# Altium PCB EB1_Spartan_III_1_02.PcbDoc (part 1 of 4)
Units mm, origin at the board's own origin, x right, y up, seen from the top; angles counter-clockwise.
Board outline 165.1 x 115.01 mm, 6 copper layers (Top Layer, MidLayer1, VCC Plane, GND Plane, MidLayer2, Bottom Layer); 356 components, 386 nets, 1788 pads, 779 vias.
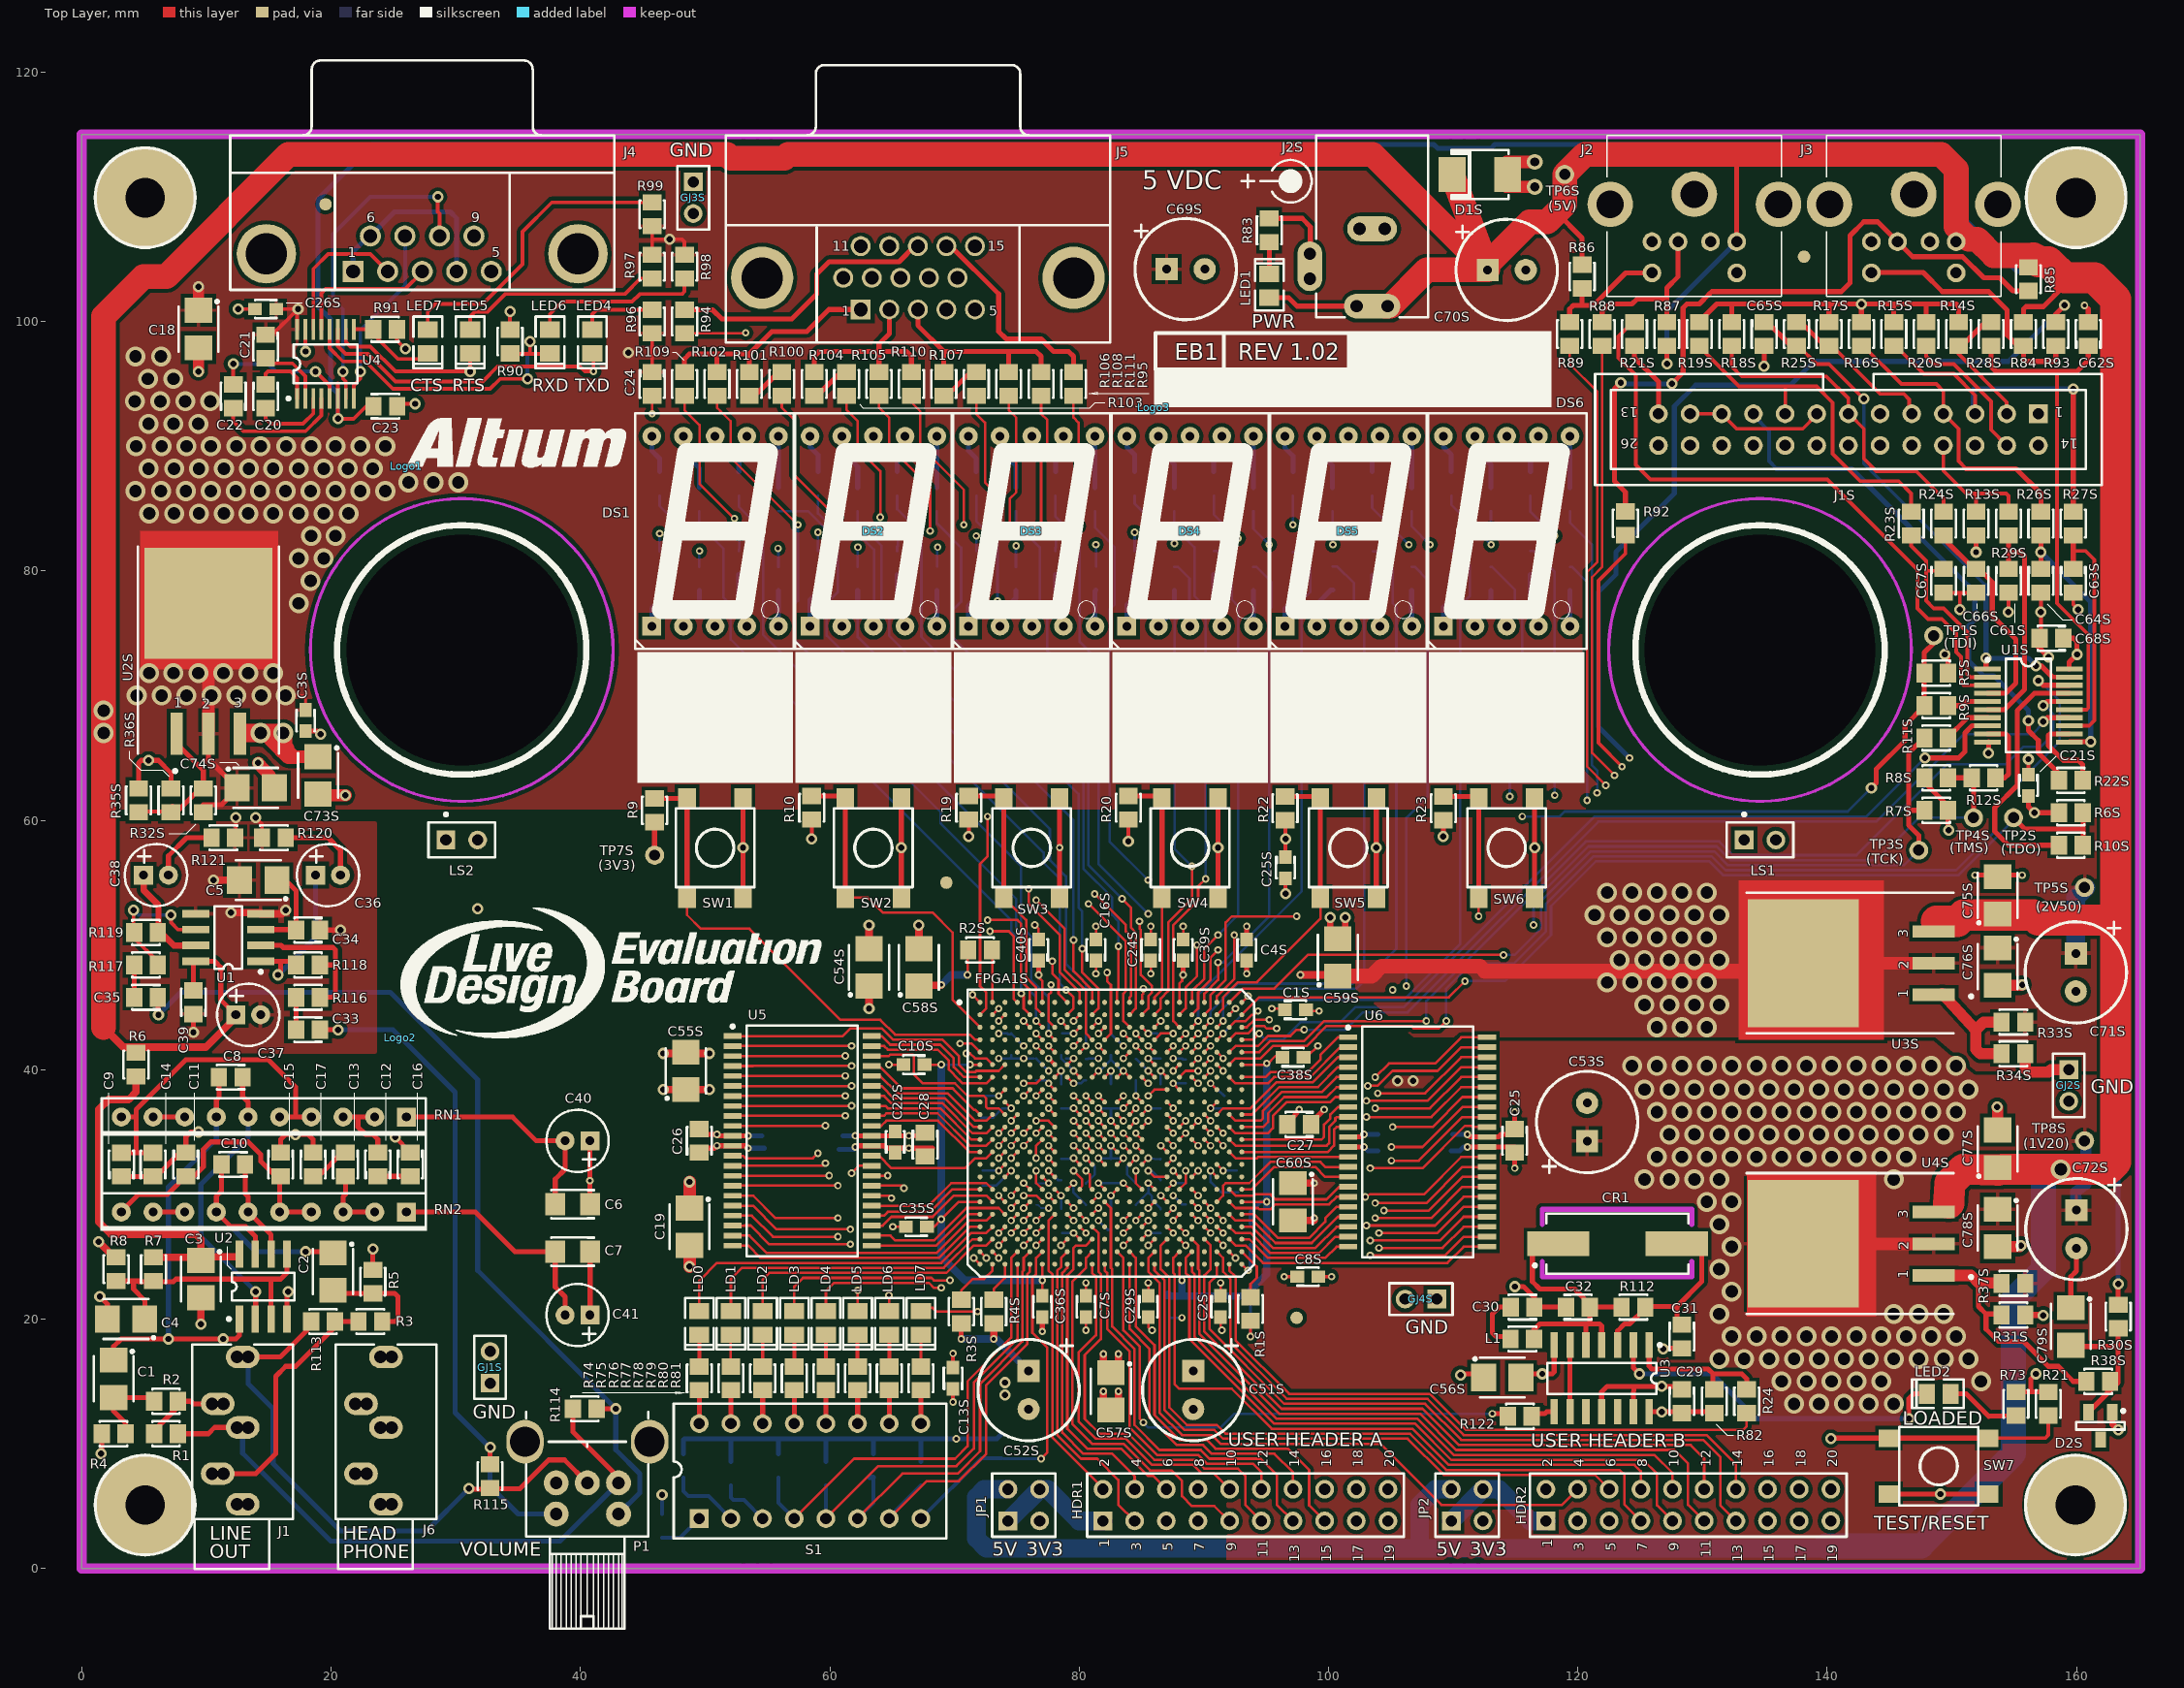
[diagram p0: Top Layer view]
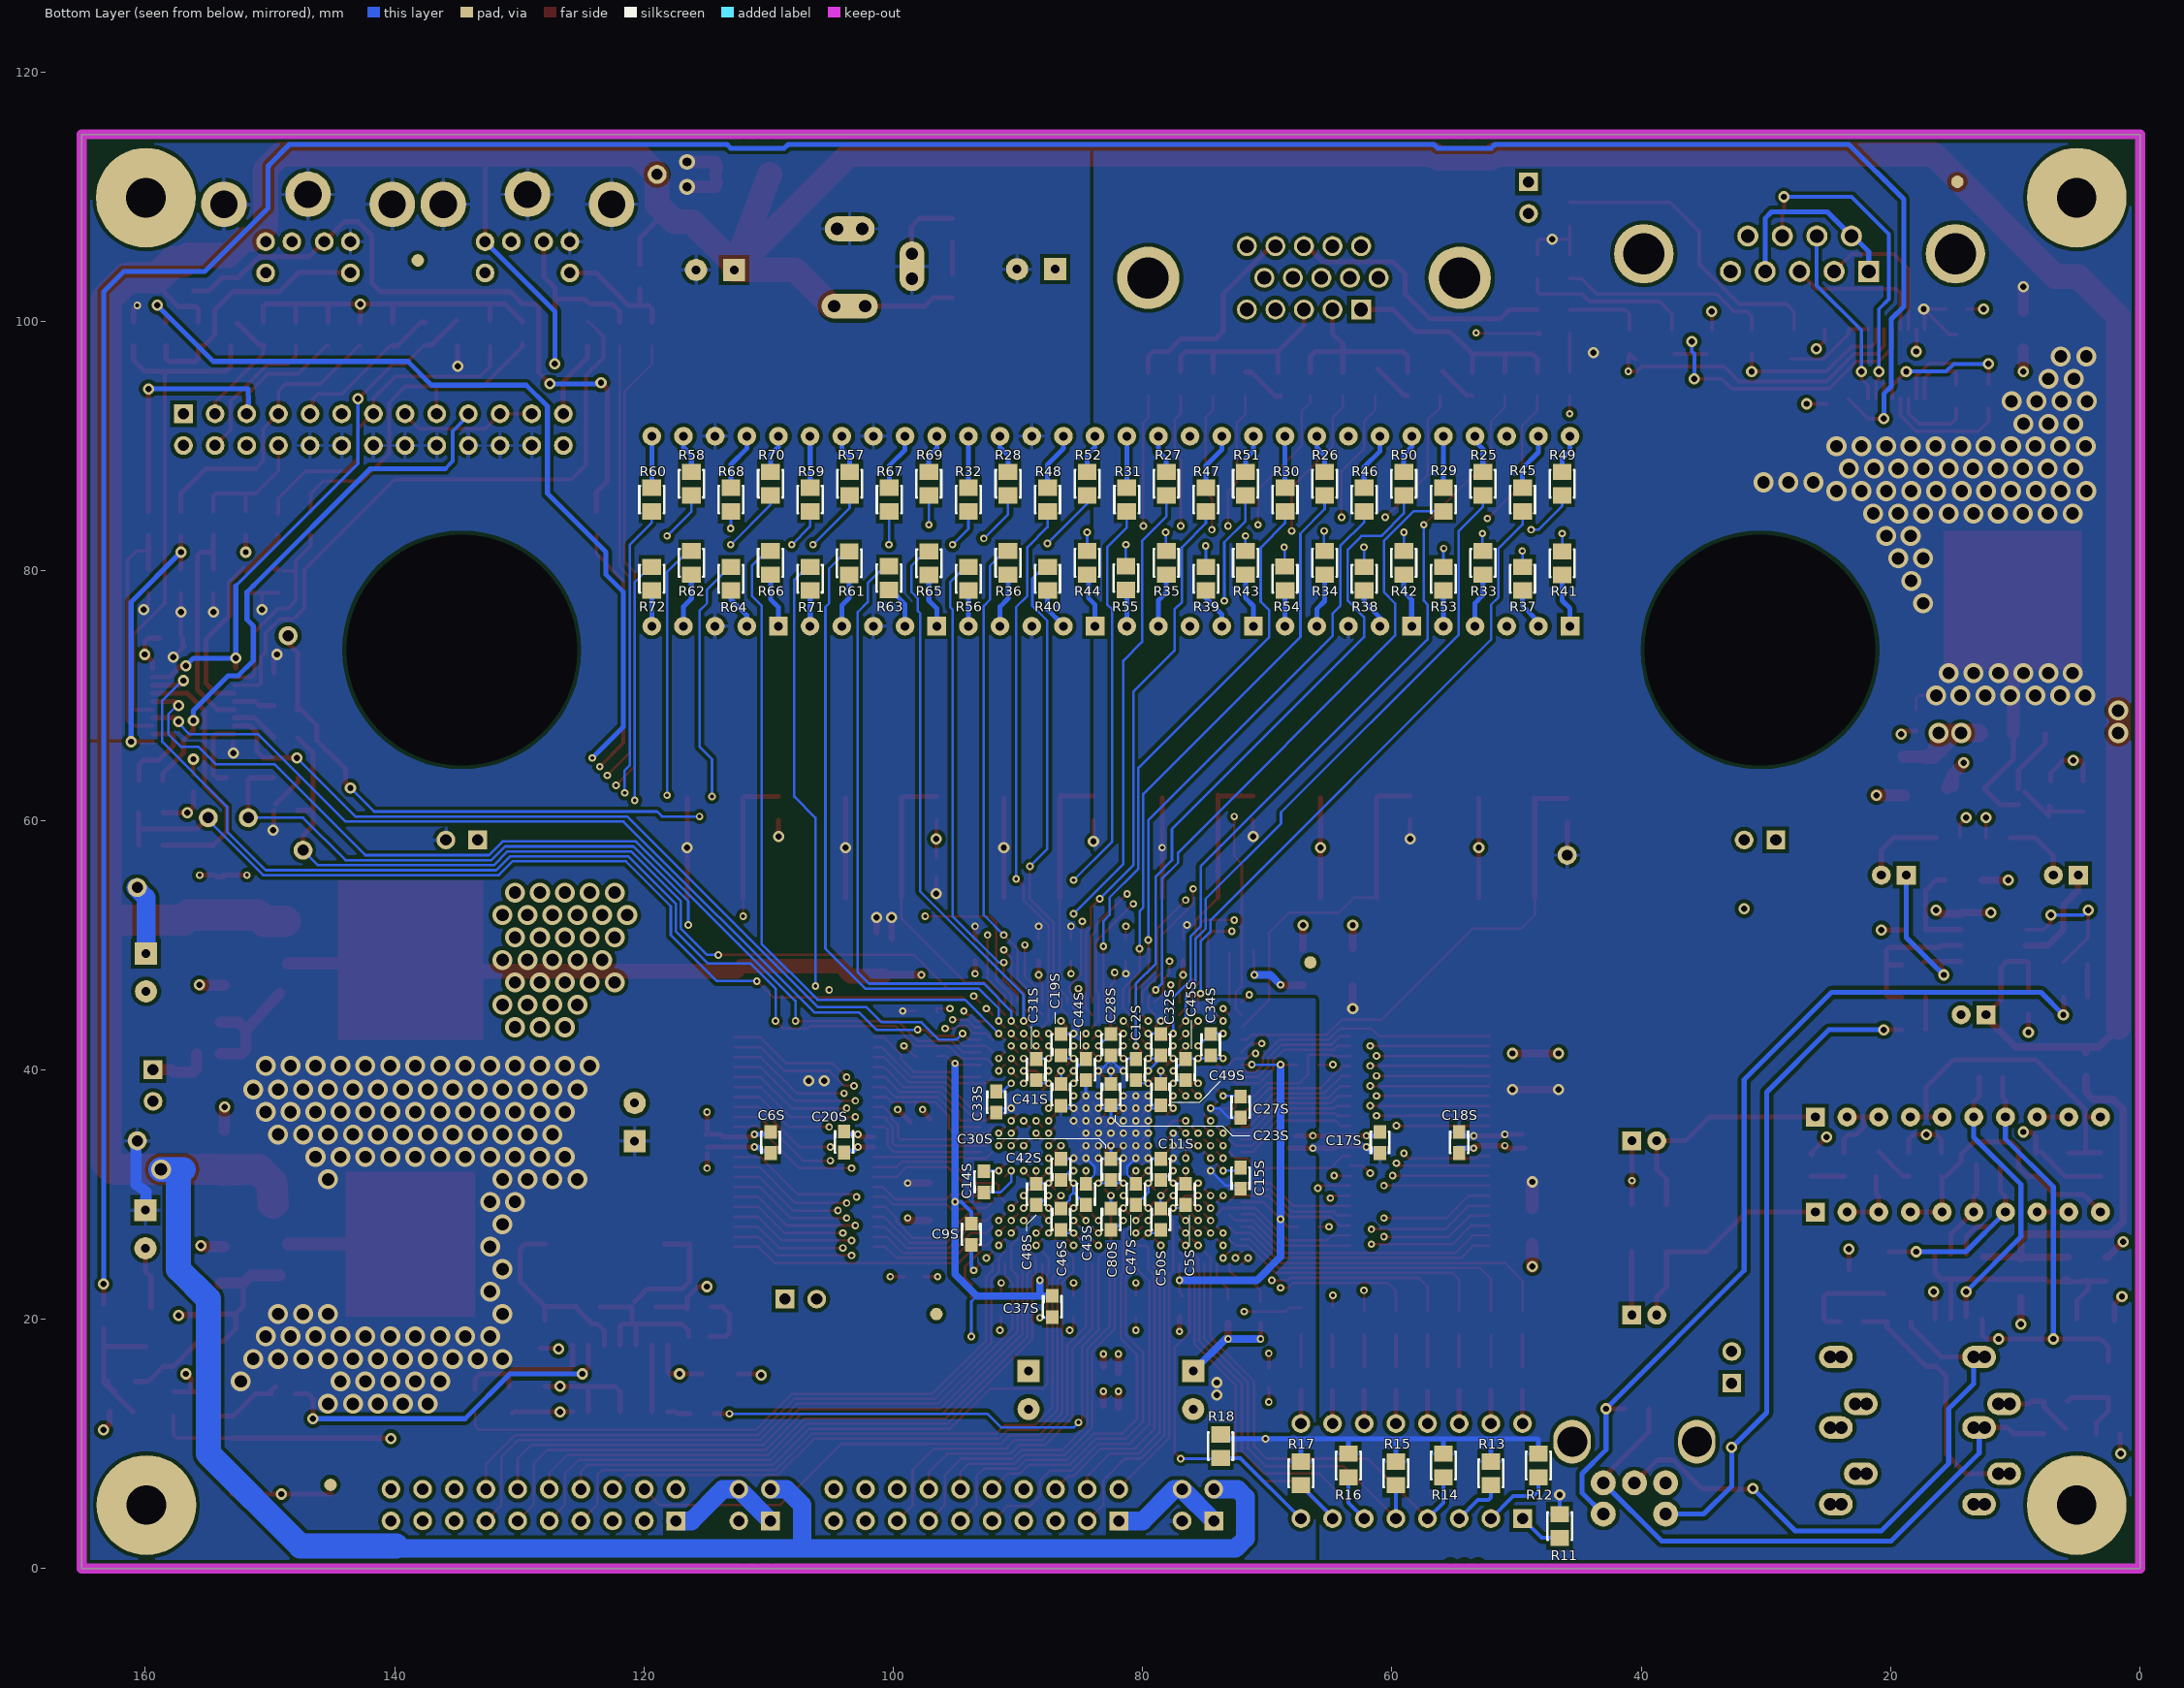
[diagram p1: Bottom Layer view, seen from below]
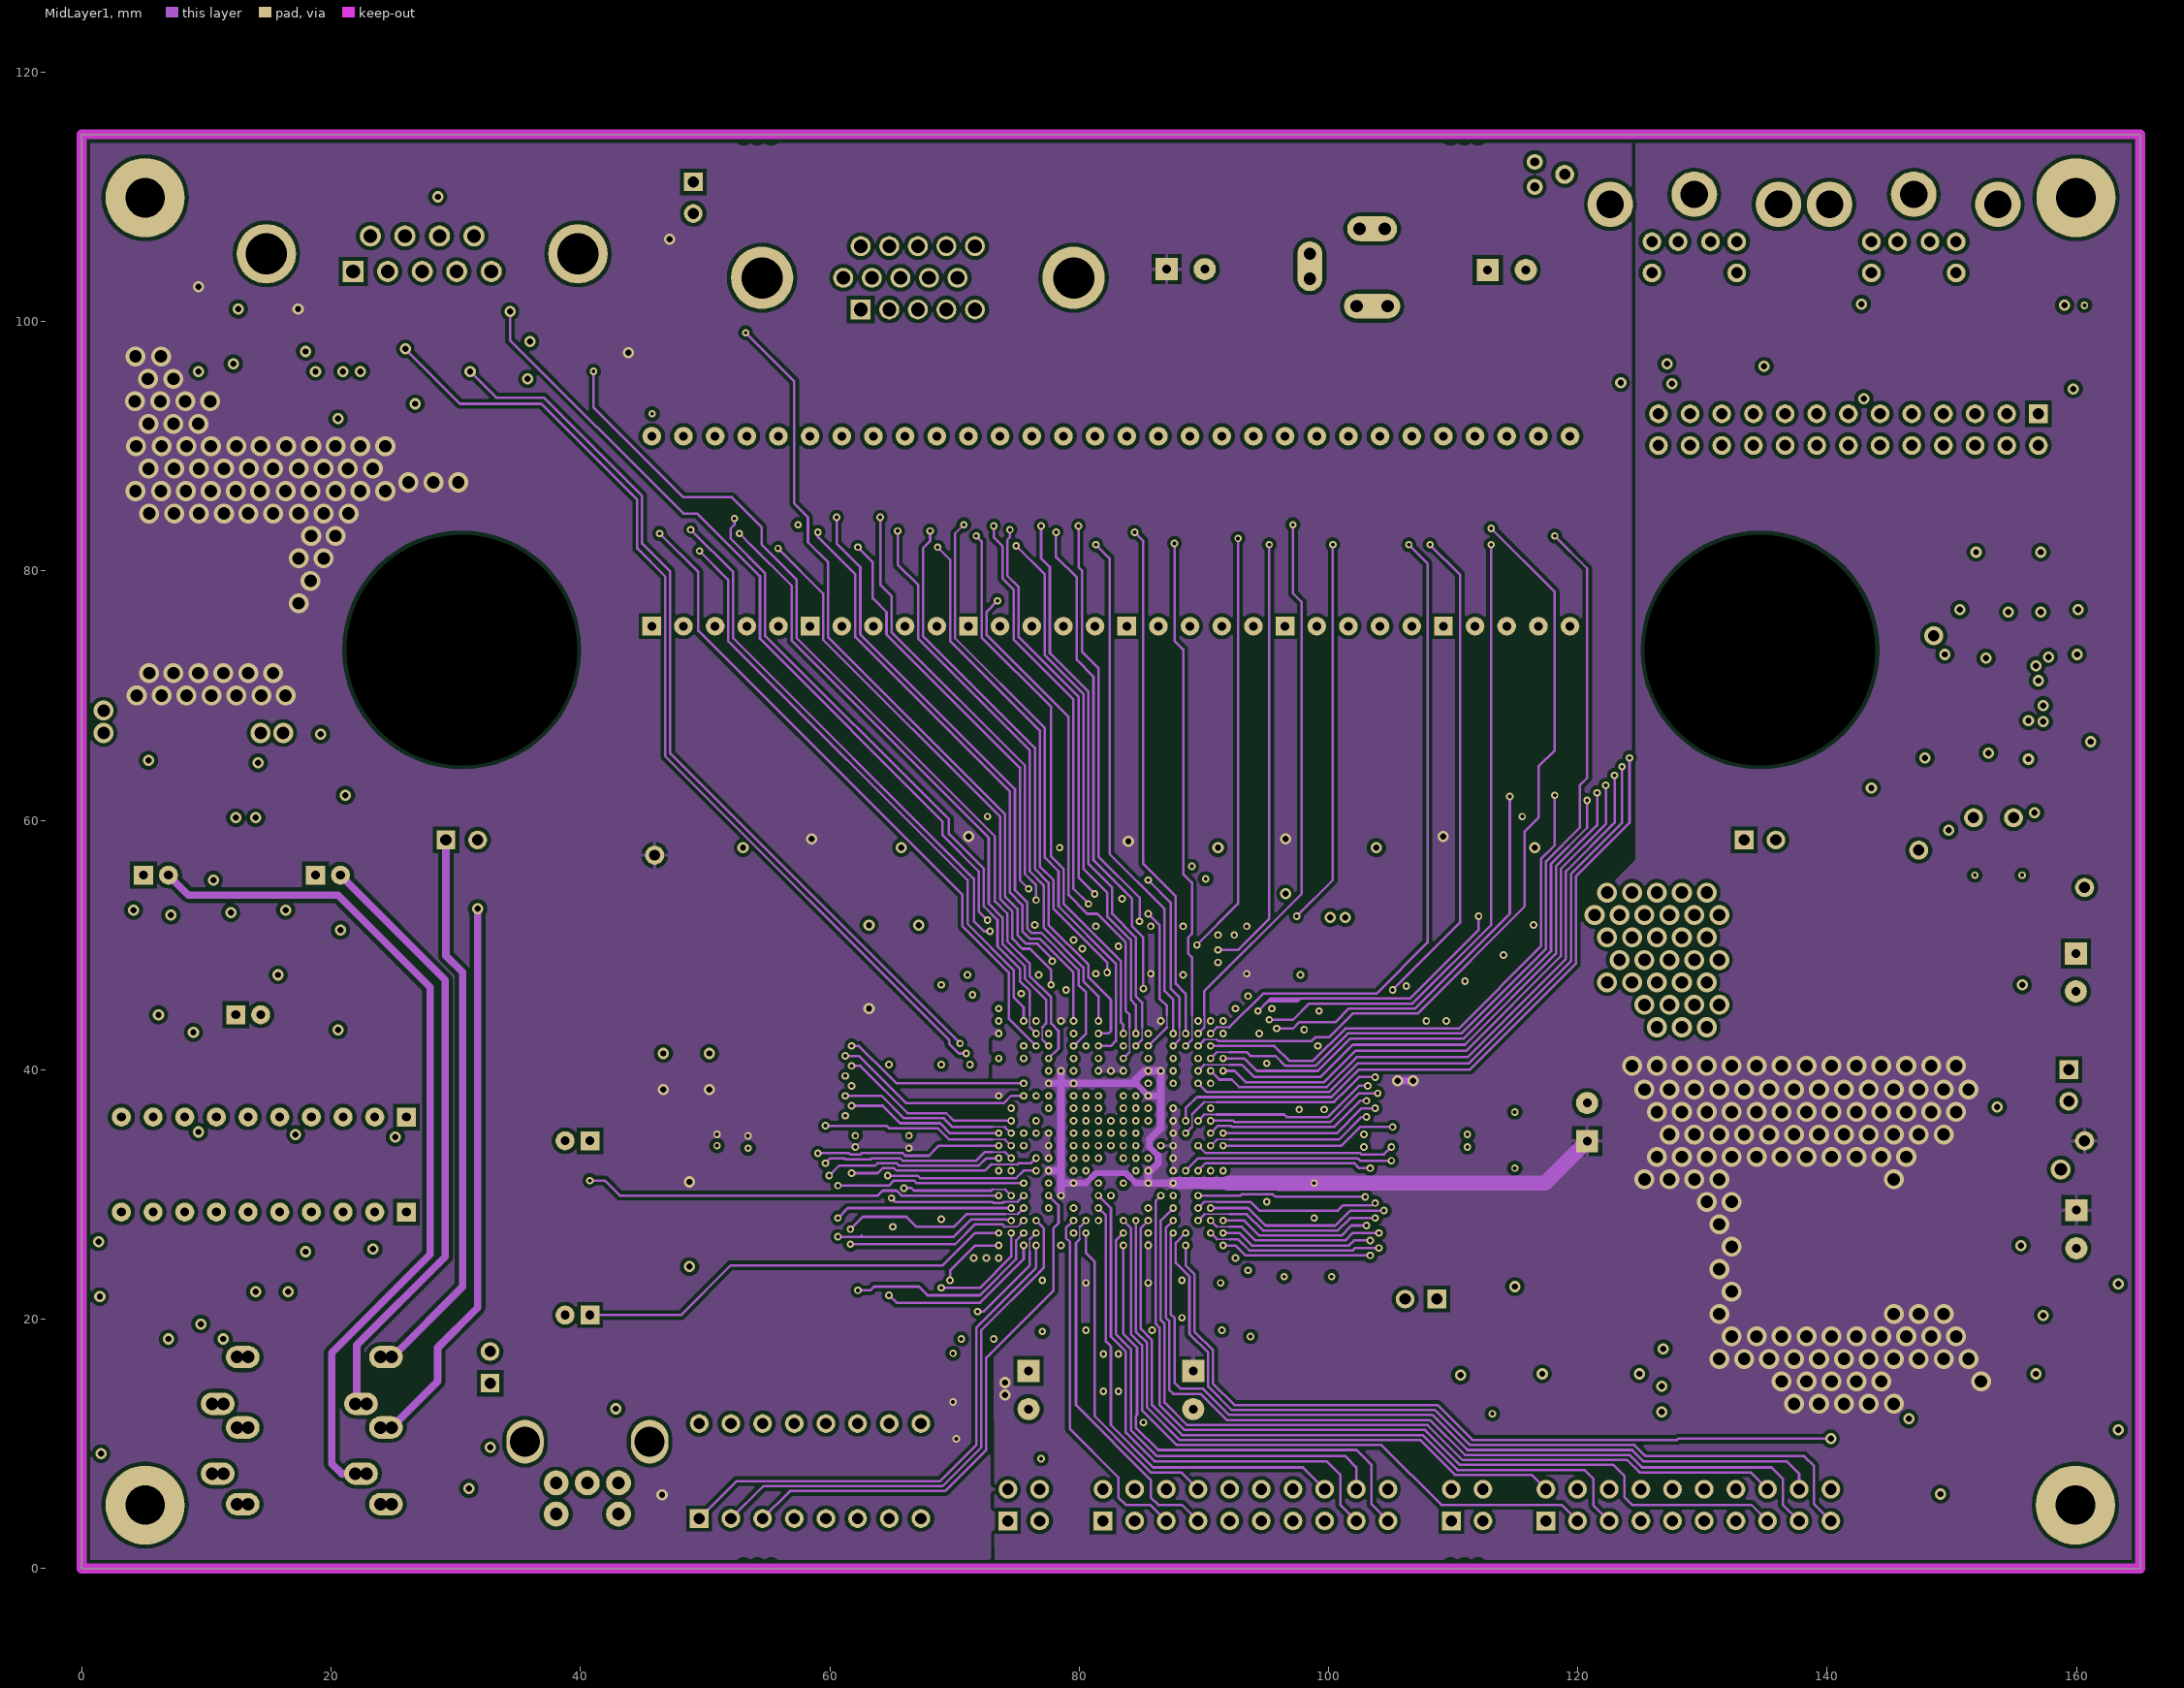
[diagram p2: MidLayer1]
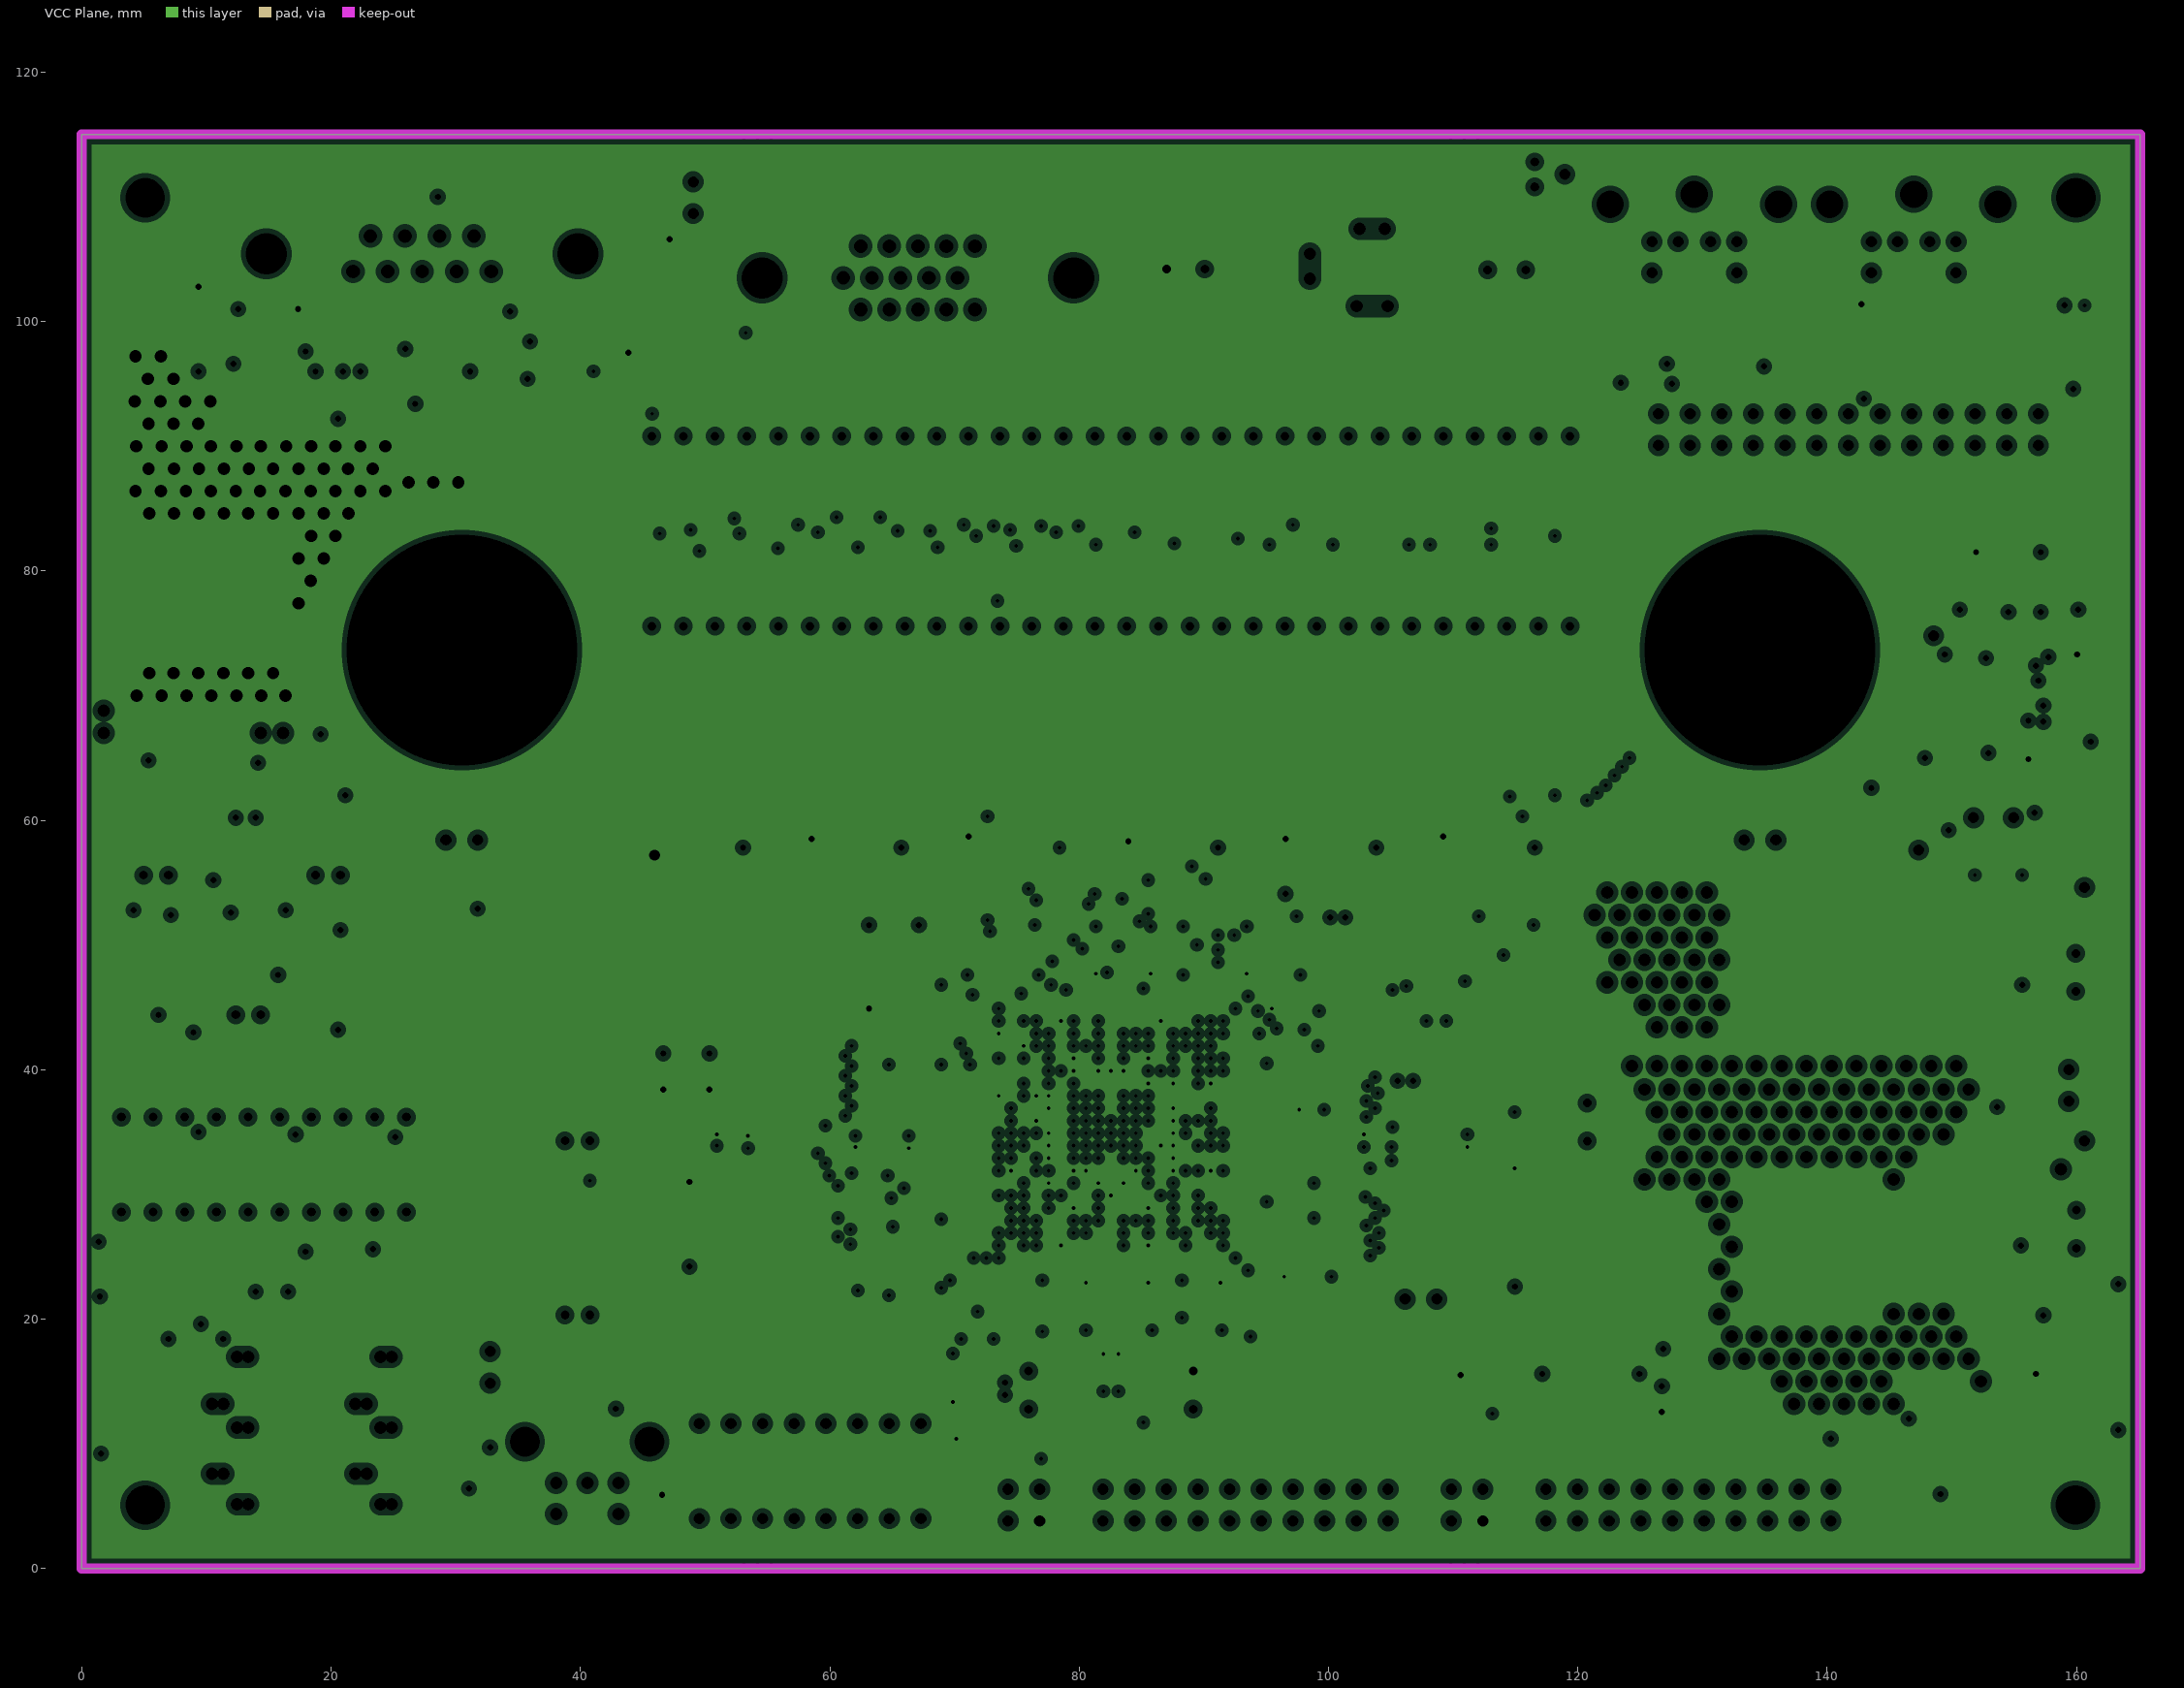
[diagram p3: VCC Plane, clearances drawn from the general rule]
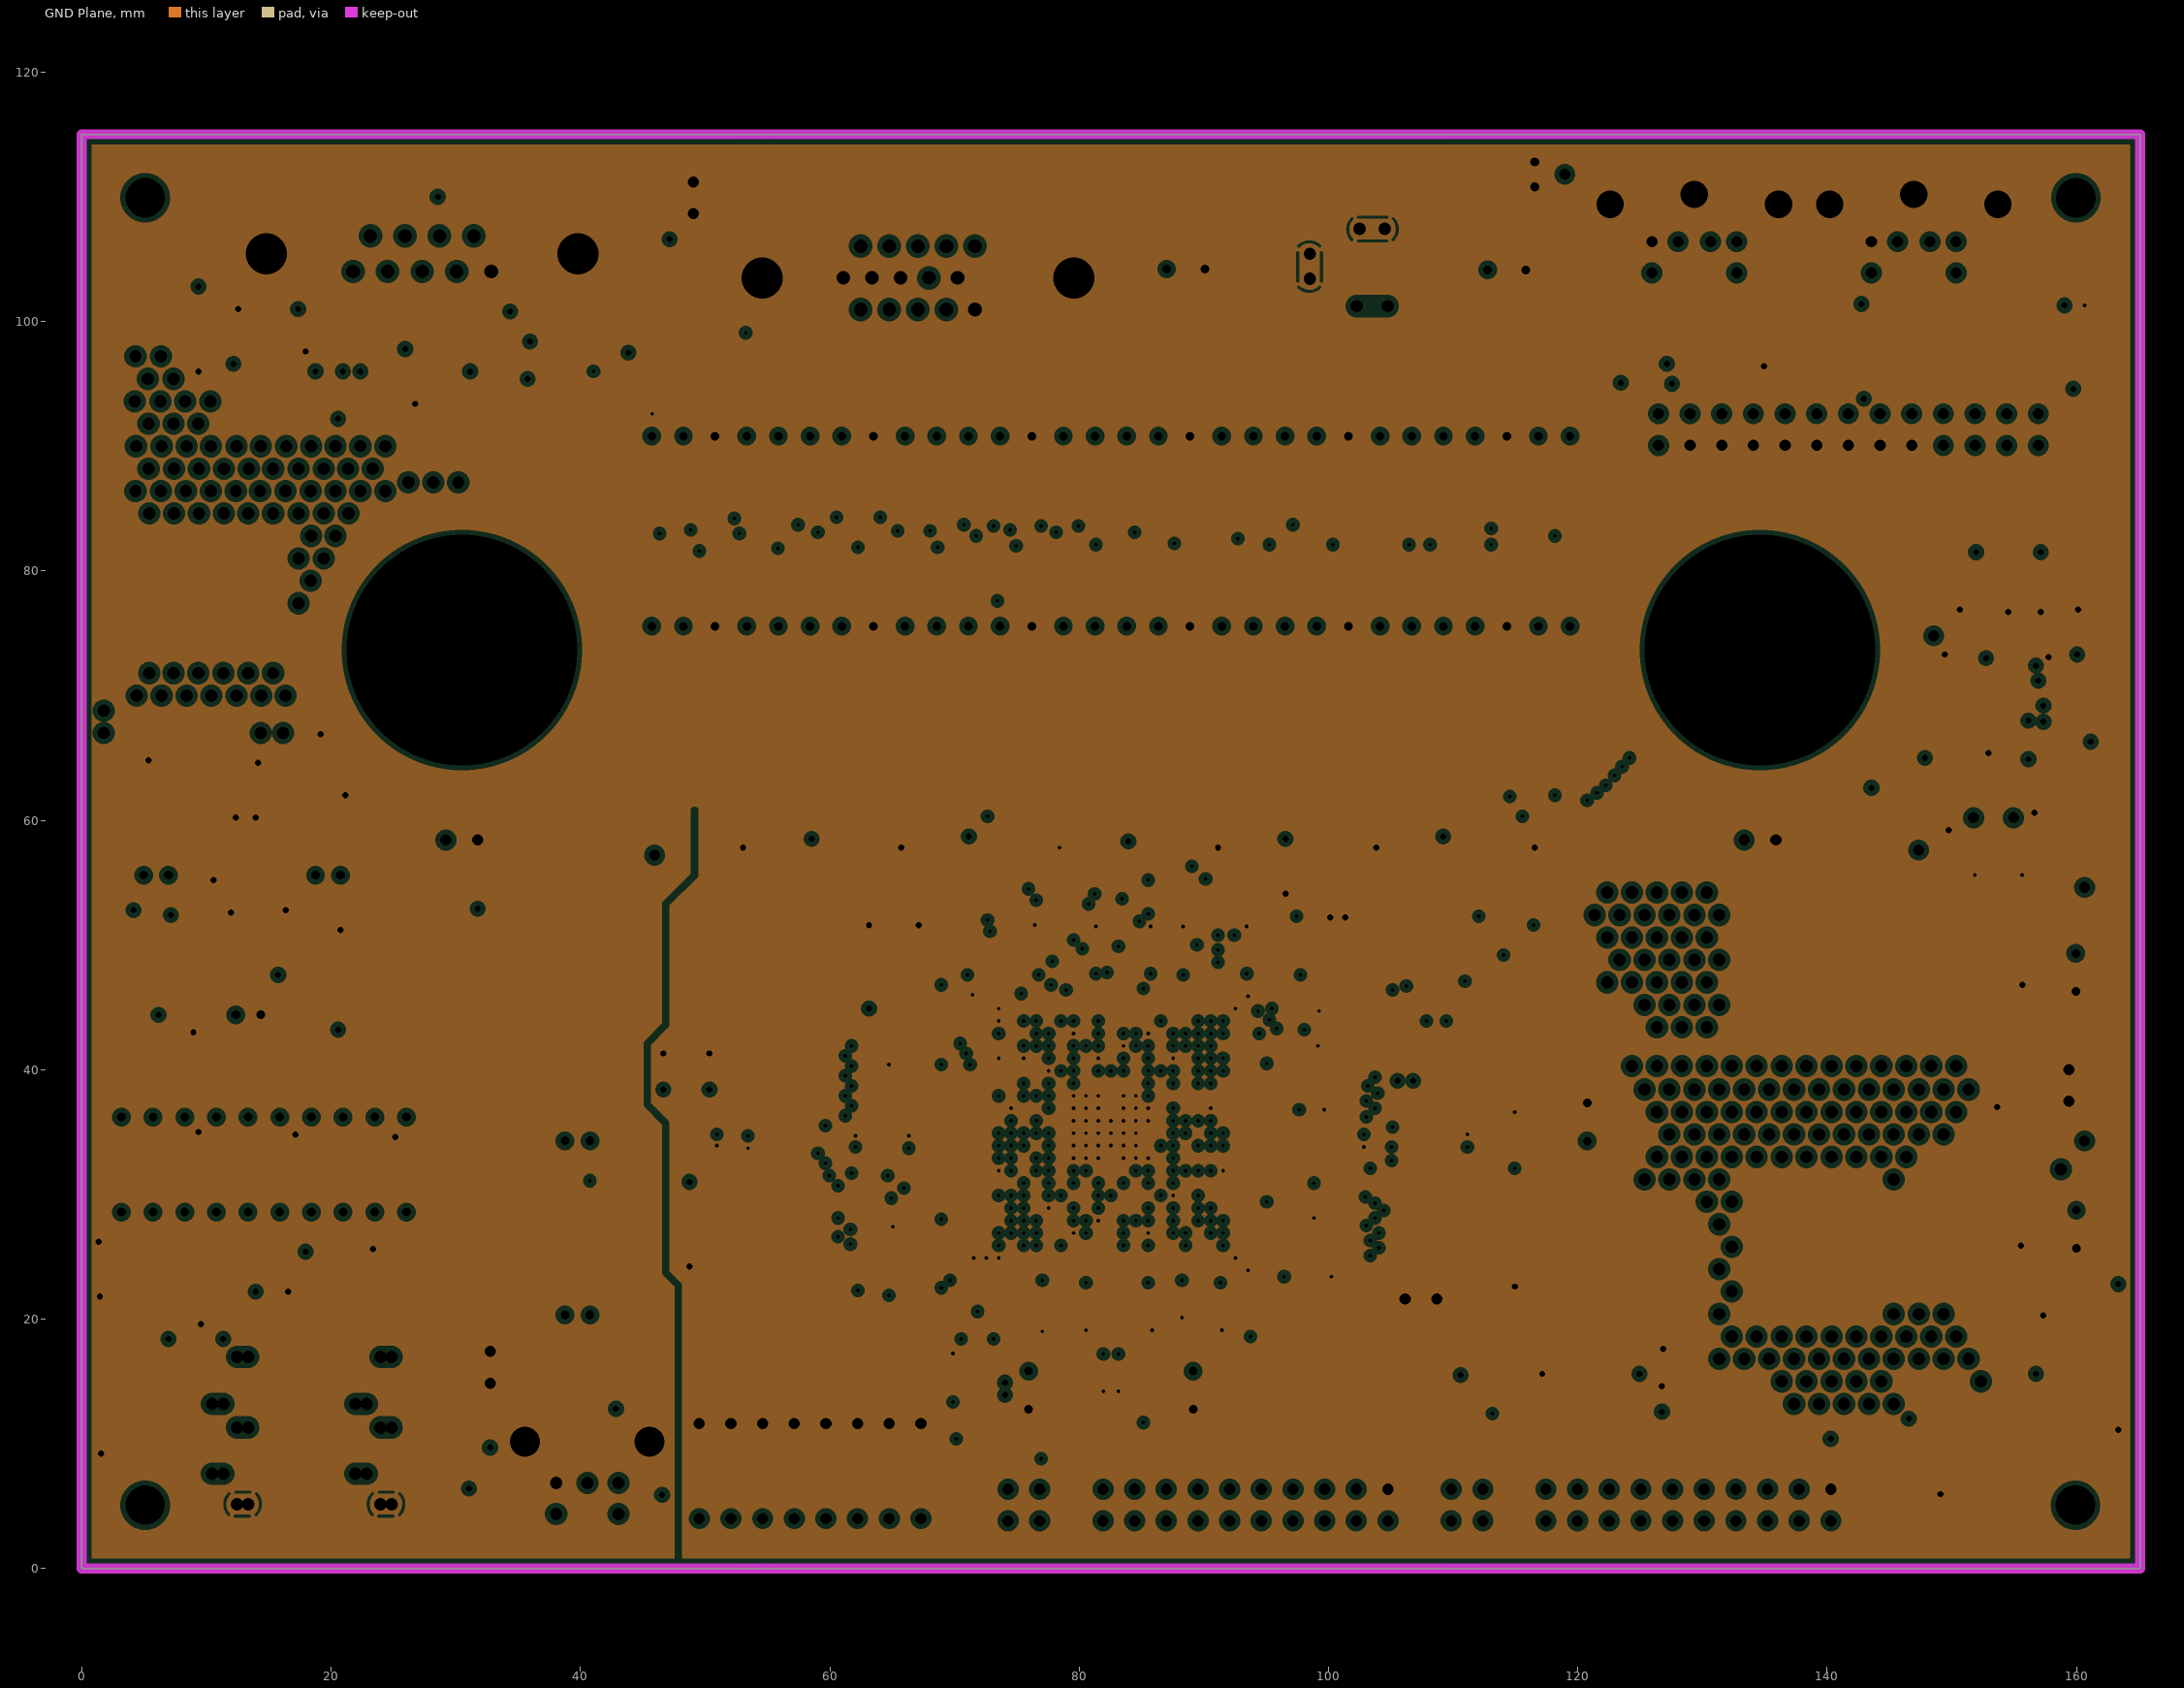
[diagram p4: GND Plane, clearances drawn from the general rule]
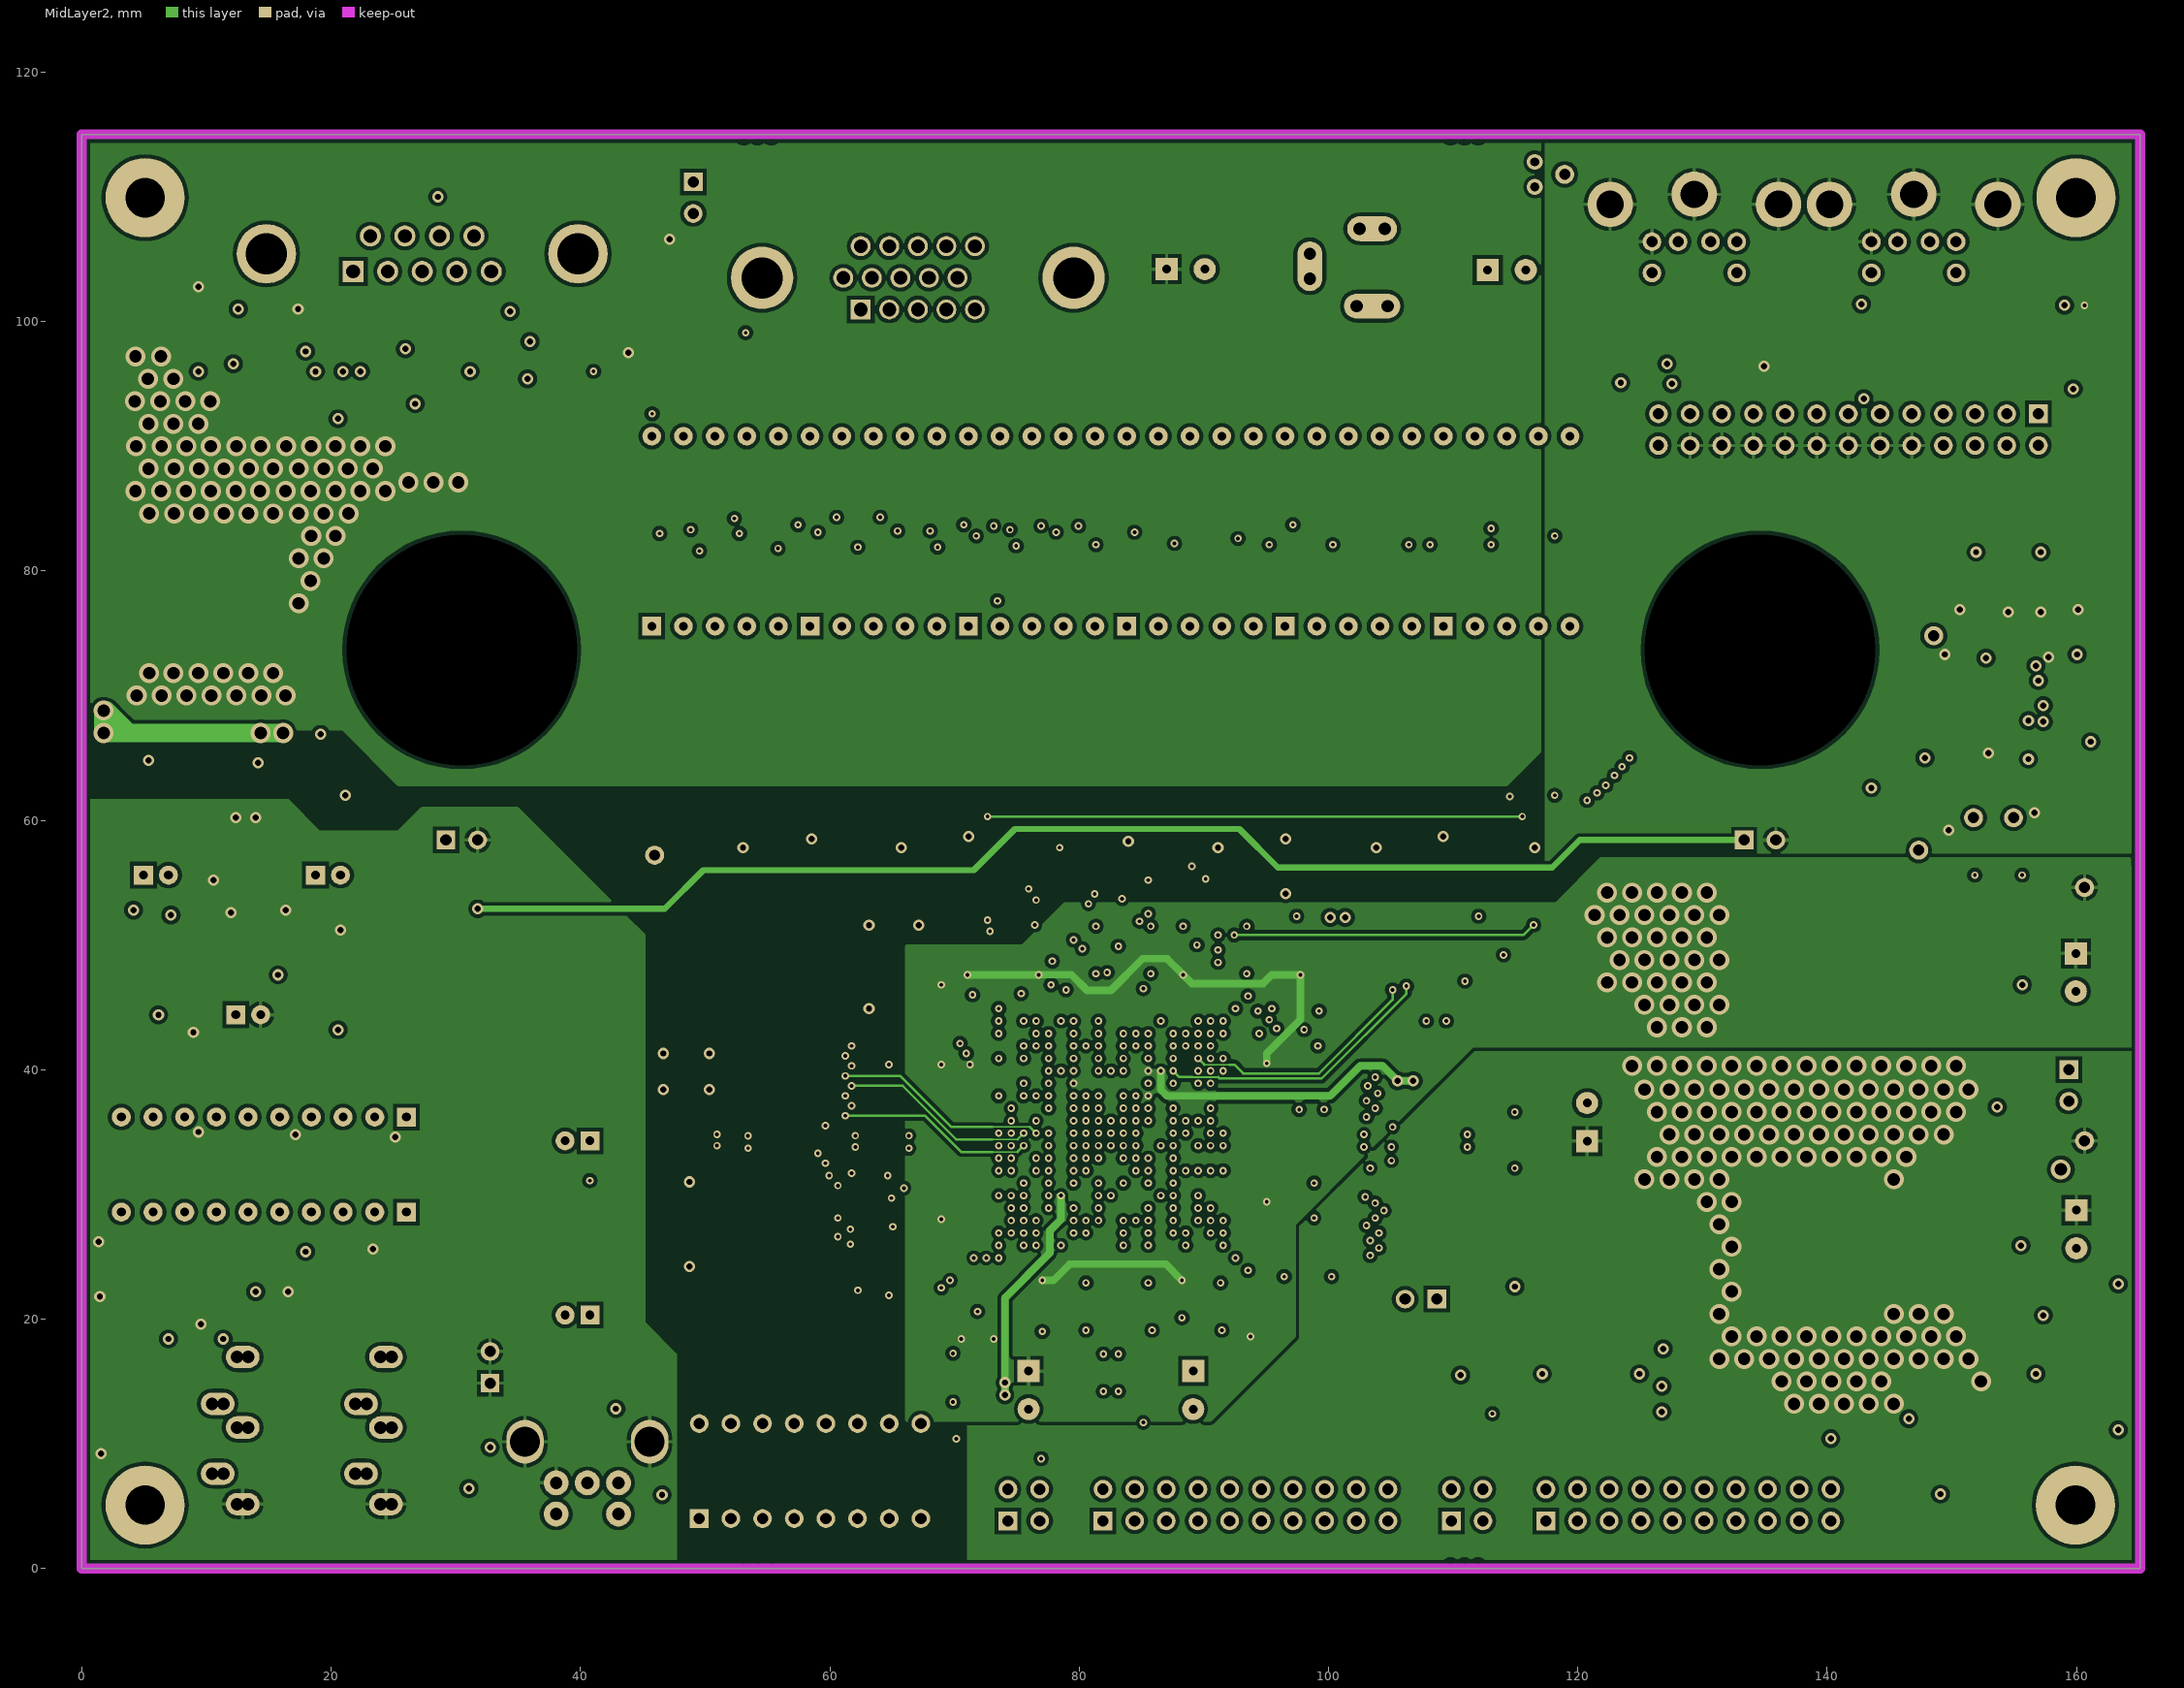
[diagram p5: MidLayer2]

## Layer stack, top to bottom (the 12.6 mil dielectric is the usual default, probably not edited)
Top Layer: signal copper 0.0356
Dielectric: core 0.32, FR-4, Dk 4.8
MidLayer1: signal copper 0.0356
Dielectric: prepreg 0.32, FR-4, Dk 4.8
VCC Plane: plane copper 0.0356, net VCC
Dielectric: core 0.32, FR-4, Dk 4.8
GND Plane: plane copper 0.0356, net GND
Dielectric: prepreg 0.32, FR-4, Dk 4.8
MidLayer2: signal copper 0.0356
Dielectric: core 0.32, FR-4, Dk 4.8
Bottom Layer: signal copper 0.0356

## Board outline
0,0 165.1,0 165.1,115.011 0,115.011

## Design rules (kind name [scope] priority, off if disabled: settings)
Clearance Clearance_Breakout_Pads [InPolygon vs IsPad && Name = 'Free-MB'] p1: gap=0.5
Clearance "Fiducial Pad Clearance" [InPadClass('Fiducial Pads')] p2: gap=2
Clearance "Speaker Pad Clearance" [InPadClass('Speaker Cutouts')] p3: gap=3
Clearance Clearance_Polygons [InPolygon] p4: gap=0.3 // Clearance should be 0.35mm
Clearance "InnerLayer Track-Via Clearance" [OnMid And IsTrack vs IsVia] p5: gap=0.127
Clearance Clearance_SSO-G20/P.65 [HasFootprint('SSO-G20/P.65') vs HasFootprint('SSO-G20/P.65')] p6: gap=0.229
Clearance "Via-Via Clearance" [IsVia vs IsVia] p7: gap=0.3
Clearance "Pad-Pad Clearance Same Net" [IsPad And Not (HasFootprint('ST-3150-5N') Or HasFootPrint('KLD-0202')) vs IsPad] p8: gap=0.254
Clearance "Via-Pad Clearance" [IsVia vs IsPad] p9: gap=0.2
Clearance "General Clearance" [All] p10: gap=0.2
ComponentClearance "7 Segment Display Clearance" [HasFootprint('SA/SC56') vs HasFootprint('SA/SC56')] p1: gap=-0.2 collisioncheckmode=3 verticalgap=0.254 showdistances=FALSE
ComponentClearance "SMD LED Clearance" [HasFootprint('SMD _LED') vs HasFootprint('SMD _LED')] p2: gap=0 collisioncheckmode=3 verticalgap=0.254 showdistances=FALSE
ComponentClearance "General ComponentClearance" [All] p3: gap=0.3 collisioncheckmode=3 verticalgap=0.254 showdistances=FALSE
FabricationTestPointUsage TestPointUsage [All] p1 off: valid=0 allowmultiple=FALSE
FabricationTestpoint Testpoint [All] p1 off: side=3 testpointundercomponent=TRUE minsize=1.016 maxsize=2.54 preferedsize=1.524 minholesize=0 maxholesize=1.016 preferedholesize=0.813 testpointgrid=0.025 allowsidetop=TRUE allowsidebottom=TRUE usegrid=TRUE gridtolerance=0
HoleSize HoleSize_Speaker [(InPadClass('Speaker Cutouts'))] p1: absolutevalues=TRUE maxlimit=18.517 minlimit=0 maxpercent=80.000 minpercent=20.000
HoleSize "HoleSize_Audio Jack" [HasFootPrint('ST-3150-5N')] p2: absolutevalues=TRUE maxlimit=2.54 minlimit=0 maxpercent=80.000 minpercent=20.000
HoleSize "HoleSize_Power Connector" [HasFootprint('KLD-0202')] p3: absolutevalues=TRUE maxlimit=2.54 minlimit=0 maxpercent=80.000 minpercent=20.000
HoleSize [All] p4: absolutevalues=TRUE maxlimit=5.2 minlimit=0.25 maxpercent=80.000 minpercent=20.000
PlaneClearance "Speaker Pad Plane Pullback" [InPadClass('Speaker Cutouts')] p1: clearance=3
PlaneClearance [All] p2: clearance=0.4
PlaneConnect PlaneConnect_Vias [IsVia] p1: planeconnectstyle=Direct reliefexpansion=0.508 reliefentries=4 reliefconductorwidth=0.254 reliefairgap=0.254
PlaneConnect PlaneConnect_Obround_Pads [InPadClass('Obround Hole Pads')] p2: planeconnectstyle=Direct reliefexpansion=0.508 reliefentries=4 reliefconductorwidth=0.254 reliefairgap=0.254
PlaneConnect [All] p3: planeconnectstyle=Relief reliefexpansion=0.5 reliefentries=4 reliefconductorwidth=0.25 reliefairgap=0.25
PolygonConnect [All] p1: connectstyle=Relief reliefconductorwidth=0.3 reliefentries=4 polygonreliefangle="90 Angle"
RoutingVias [All] p1: holewidth=0.3 width=0.6 viastyle="Through Hole" minholewidth=0.3 minwidth=0.6 maxholewidth=1.016 maxwidth=1.6
SilkscreenOverComponentPads [All] p1: minsilkscreentomaskgap=0.254
SolderMaskExpansion SolderMaskExpansion_Vias [IsVia] p1: expansion=-0.65
SolderMaskExpansion [All] p2: expansion=0.1
Width [All] p1: maxlimit=2.502 minlimit=0.127 preferedwidth=0.3 toplayer_minwidth=0.2 toplayer_prefwidth=0.4 midlayer1_prefwidth=0.127 midlayer2_prefwidth=0.2 minimp=50.000000 maximp=50.000000 favimp=50.000000
21 further rules are at their usual default settings.

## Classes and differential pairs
component class U_NEB_SRAM: C25 C26 C27 C28 U5 U6
pad class "Fiducial Pads": Free-PSM
net class LED[7..0]: LED0 LED1 LED2 LED3 LED4 LED5 LED6 LED7
net class DIG5_SEG[7..0]: DIG5_SEG0 DIG5_SEG1 DIG5_SEG2 DIG5_SEG3 DIG5_SEG4 DIG5_SEG5 DIG5_SEG6 DIG5_SEG7
net class DIG4_SEG[7..0]: DIG4_SEG0 DIG4_SEG1 DIG4_SEG2 DIG4_SEG3 DIG4_SEG4 DIG4_SEG5 DIG4_SEG6 DIG4_SEG7
net class SW_USER[5..0]: SW_USER0 SW_USER1 SW_USER2 SW_USER3 SW_USER4 SW_USER5
net class SW_DIP[7..0]: SW_DIP0 SW_DIP1 SW_DIP2 SW_DIP3 SW_DIP4 SW_DIP5 SW_DIP6 SW_DIP7
net class SRAM1_D[15..0]: SRAM1_D0 SRAM1_D1 SRAM1_D2 SRAM1_D3 SRAM1_D4 SRAM1_D5 SRAM1_D6 SRAM1_D7 SRAM1_D8 SRAM1_D9 SRAM1_D10 SRAM1_D11 SRAM1_D12 SRAM1_D13 SRAM1_D14 SRAM1_D15
net class SRAM1_A[18..0]: SRAM1_A0 SRAM1_A1 SRAM1_A2 SRAM1_A3 SRAM1_A4 SRAM1_A5 SRAM1_A6 SRAM1_A7 SRAM1_A8 SRAM1_A9 SRAM1_A10 SRAM1_A11 SRAM1_A12 SRAM1_A13 SRAM1_A14 SRAM1_A15 SRAM1_A16 SRAM1_A17 SRAM1_A18
net class SRAM0_D[15..0]: SRAM0_D0 SRAM0_D1 SRAM0_D2 SRAM0_D3 SRAM0_D4 SRAM0_D5 SRAM0_D6 SRAM0_D7 SRAM0_D8 SRAM0_D9 SRAM0_D10 SRAM0_D11 SRAM0_D12 SRAM0_D13 SRAM0_D14 SRAM0_D15
net class SRAM0_A[18..0]: SRAM0_A0 SRAM0_A1 SRAM0_A2 SRAM0_A3 SRAM0_A4 SRAM0_A5 SRAM0_A6 SRAM0_A7 SRAM0_A8 SRAM0_A9 SRAM0_A10 SRAM0_A11 SRAM0_A12 SRAM0_A13 SRAM0_A14 SRAM0_A15 SRAM0_A16 SRAM0_A17 SRAM0_A18
net class RED[2..0]: RED0 RED1 RED2
net class IO[35..0]: IO0 IO1 IO2 IO3 IO4 IO5 IO6 IO7 IO8 IO9 IO10 IO11 IO12 IO13 IO14 IO15 IO16 IO17 IO18 IO19 IO20 IO21 IO22 IO23 IO24 IO25 IO26 IO27 IO28 IO29 IO30 IO31 IO32 IO33 IO34 IO35
net class GREEN[2..0]: GREEN0 GREEN1 GREEN2
net class DIG3_SEG[7..0]: DIG3_SEG0 DIG3_SEG1 DIG3_SEG2 DIG3_SEG3 DIG3_SEG4 DIG3_SEG5 DIG3_SEG6 DIG3_SEG7
net class DIG2_SEG[7..0]: DIG2_SEG0 DIG2_SEG1 DIG2_SEG2 DIG2_SEG3 DIG2_SEG4 DIG2_SEG5 DIG2_SEG6 DIG2_SEG7
net class DIG1_SEG[7..0]: DIG1_SEG0 DIG1_SEG1 DIG1_SEG2 DIG1_SEG3 DIG1_SEG4 DIG1_SEG5 DIG1_SEG6 DIG1_SEG7
net class DIG0_SEG[7..0]: DIG0_SEG0 DIG0_SEG1 DIG0_SEG2 DIG0_SEG3 DIG0_SEG4 DIG0_SEG5 DIG0_SEG6 DIG0_SEG7
net class BLUE[2..0]: BLUE0 BLUE1 BLUE2
component class U_NEB_USRIO: HDR1 HDR2 JP1 JP2
component class U_NEB_PSU: C69S C70S C71S C72S C73S C74S C75S C76S C77S C78S C79S D1S D2S GJ1S GJ2S GJ3S GJ4S J2S R30S R31S R32S R33S R34S R35S R36S R37S R38S TP5S TP6S TP7S TP8S U2S U3S U4S
component class U_NEB_PCIO: C18 C19 C20 C21 C22 C23 C24 J2 J3 J4 J5 LED4 LED5 LED6 LED7 R84 R85 R86 R87 R88 R89 R90 R91 R92 R93 R94 R95 R96 R97 R98 R99 R100 R101 R102 R103 R104 R105 R106 R107 R108 R109 R110 R111 U4
component class U_NEB_LED_KEY: DS1 DS2 DS3 DS4 DS5 DS6 L0 L2 L3 L4 L5 L6 L7 LD0 LD1 LD2 LD3 LD4 LD5 LD6 LD7 LED1 LED2 R9 R10 R11 R12 R13 R14 R15 R16 R17 R18 R19 R20 R21 R22 R23 R24 R25 R26 R27 R28 R29 R30 R31 R32 R33 R34 R35 R36 R37 R38 R39 R40 R41 R42 R43 R44 R45 R46 R47 R48 R49 R50 R51 R52 R53 R54 R55 R56 R57 R58 R59 R60 R61 R62 R63 R64 R65 R66 R67 R68 R69 R70 R71 R72 R73 R74 R75 R76 R77 R78 R79 R80 R81 R82 R83 S1 SW1 SW2 SW3 SW4 SW5 SW6 SW7 U3
component class U_NEB_JTAG_INT: C61S C62S C63S C64S C65S C66S C67S C68S J1S R13S R14S R15S R16S R17S R18S R19S R20S R21S R22S R23S R24S R25S R26S R27S R28S R29S U1S
component class U_NEB_AUDIO_OUT: C1 C2 C3 C4 C5 C6 C7 C8 C9 C10 C11 C12 C13 C14 C15 C16 C17 C33 C34 C35 C36 C37 C38 C39 C40 C41 J1 J6 LS1 LS2 LS3 LS4 P1 R1 R2 R3 R4 R5 R6 R7 R8 R113 R114 R115 R116 R117 R118 R119 R120 R121 RN1 RN2 SPKR1 U1 U2
component class U_FPGA: C1S C2S C3S C4S C5S C6S C7S C8S C9S C10S C11S C12S C13S C14S C15S C16S C17S C18S C19S C20S C21S C22S C23S C24S C25S C26S C27S C28S C29S C30S C31S C32S C33S C34S C35S C36S C37S C38S C39S C40S C41S C42S C43S C44S C45S C46S C47S C48S C49S C50S C51S C52S C53S C54S C55S C56S C57S C58S C59S C60S C80S FPGA1S R1S R2S R3S R4S R5S R6S R7S R8S R9S R10S R11S R12S TP1S TP2S TP3S TP4S
pad class "Speaker Cutouts": Free-H-SPK2 Free-H_SPK1
pad class "Obround Hole Pads": J1-1 J1-1A J1-1B J1-2 J1-2A J1-2B J1-3 J1-3A J1-3B J1-4 J1-4A J1-4B J1-5 J1-5A J1-5B J2S-1 J2S-1A J2S-1B J2S-2 J2S-2A J2S-2B J2S-3 J2S-3A J2S-3B J6-1 J6-1A J6-1B J6-2 J6-2A J6-2B J6-3 J6-3A J6-3B J6-4 J6-4A J6-4B J6-5 J6-5A J6-5B

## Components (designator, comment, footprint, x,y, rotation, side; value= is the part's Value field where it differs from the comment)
C1 "10uF" MCCT-B#1 2.55,15.2 r270 top
C1S "220nF" CC1608-0603#1 97.35,44.8 r0 top
C2 "10uF" MCCT-B#1 20.15,23.8 r270 top
C2S "220nF" CC1608-0603#1 91.35,21 r270 top
C3 "10uF" MCCT-B#1 9.55,23.2 r270 top
C3S "220nF" CC1608-0603#1 17.95,68 r270 top
C4 "10uF" MCCT-B#1 3.55,20 r180 top
C4S "220nF" CC1608-0603#1 93.45,49.6 r90 top
C5 "10uF" MCCT-B#1 14.15,55.2 r180 top
C5S "220nF" CC1608-0603#1 76.55,30 r270 bottom
C6 "1uF" CC3216-1206 39.37,29.21 r180 top
C6S "220nF" CC1608-0603#1 109.855,34.163 r90 bottom
C7 "1uF" CC3216-1206 39.37,25.4 r180 top
C7S "220nF" CC1608-0603#1 80.55,21 r270 top
C8 "470pF" CC2012-0805 11.95,39.4 r180 top
C8S "220nF" CC1608-0603#1 98.35,23.4 r0 top
C9 "470pF" CC2012-0805 3.175,32.385 r90 top
C9S "220nF" CC1608-0603#1 93.75,26.8 r270 bottom
C10 "470pF" CC2012-0805 12.15,32.4 r180 top
C10S "220nF" CC1608-0603#1 66.75,40.4 r180 top
C11 "470pF" CC2012-0805 8.35,32.4 r270 top
C11S "220nF" CC1608-0603#1 78.55,32 r90 bottom
C12 "6.8nF" CC2012-0805 23.75,32.4 r90 top
C12S "220nF" CC1608-0603#1 80.55,40 r90 bottom
C13 "6.8nF" CC2012-0805 21.15,32.4 r270 top
C13S "10nF" CC1608-0603#1 69.885,15.245 r90 top
C14 "4.7nF" CC2012-0805 5.715,32.385 r90 top
C14S "10nF" CC1608-0603#1 92.75,31 r90 bottom
C15 "4.7nF" CC2012-0805 15.95,32.4 r270 top
C15S "10nF" CC1608-0603#1 72.15,31.3 r90 bottom
C16 "47nF" CC2012-0805 26.35,32.4 r270 top
C16S "10nF" CC1608-0603#1 81.35,49.6 r90 top
C17 "47nF" CC2012-0805 18.55,32.4 r270 top
C17S "10nF" CC1608-0603#1 60.96,34.163 r90 bottom
C18 "10uF" MCCT-B#1 9.35,99.4 r270 top
C18S "10nF" CC1608-0603#1 54.61,34.163 r270 bottom
C19 "10uF" MCCT-B#1 48.75,27.4 r270 top
C19S "10nF" CC1608-0603#1 86.55,42 r90 bottom
C20 "100nF" CC2012-0805 14.75,94 r270 top
C20S "10nF" CC1608-0603#1 103.95,34.2 r270 bottom
C21 "100nF" CC2012-0805 14.75,98 r270 top
C21S "10nF" CC1608-0603#1 156.15,62.8 r270 top
C22 "100nF" CC2012-0805 12.15,94 r90 top
C22S "10nF" CC1608-0603#1 65.25,34.2 r90 top
C23 "100nF" CC2012-0805 24.35,93.2 r0 top
C23S "10nF" CC1608-0603#1 82.55,38 r270 bottom
C24 "100nF" CC2012-0805 45.75,95 r270 top
C24S "10nF" CC1608-0603#1 85.75,49.6 r90 top
C25 "220nF" CC2012-0805 114.935,34.29 r270 top
C25S "10nF" CC1608-0603#1 96.55,56.2 r270 top
C26 "220nF" CC2012-0805 49.53,34.29 r90 top
C26S "10nF" CC1608-0603#1 14.75,101 r180 top
C27 "10nF" CC2012-0805 97.65,35.6 r180 top
C27S "10nF" CC1608-0603#1 72.15,37 r270 bottom
C28 "10nF" CC2012-0805 67.65,34 r270 top
C28S "10nF" CC1608-0603#1 82.55,42 r90 bottom
C29 "10nF" CC2012-0805 128.35,13.4 r270 top
C29S "10nF" CC1608-0603#1 85.55,21 r270 top
C30 "1nF/NPO" CC2012-0805 115.57,20.955 r180 top
C30S "10nF" CC1608-0603#1 82.55,32 r90 bottom
C31 "15pF/NPO" CC2012-0805 128.35,18.6 r270 top
C31S "10nF" CC1608-0603#1 88.55,40 r90 bottom
C32 "15pF/NPO" CC2012-0805 120.015,20.955 r0 top
C32S "10nF" CC1608-0603#1 78.55,42 r90 bottom
C33 "0.1uF" CC2012-0805 18.15,43.2 r180 top
C33S "10nF" CC1608-0603#1 91.75,37.4 r270 bottom
C34 "0.1uF" CC2012-0805 18.15,51.2 r180 top
C34S "10nF" CC1608-0603#1 74.55,42 r270 bottom
C35 "0.1uF" CC2012-0805 5.15,45.8 r180 top
C35S "10nF" CC1608-0603#1 66.95,27.4 r180 top
C36 "100uF/10V" "CAP D5MM/P2MM" 18.75,55.6 r0 top
C36S "10nF" CC1608-0603#1 77.05,21 r270 top
C37 "100uF/10V" "CAP D5MM/P2MM" 12.35,44.4 r0 top
C37S "10nF" CC1608-0603#1 87.25,21 r270 bottom
C38 "100uF/10V" "CAP D5MM/P2MM" 4.95,55.6 r0 top
C38S "10nF" CC1608-0603#1 97.15,41 r0 top
C39 "0.1uF" CC2012-0805 8.95,45.4 r90 top
C39S "10nF" CC1608-0603#1 88.35,49.6 r90 top
C40 "2.2uF/50V/Bip" "CAP D5mm/P2mm" 40.767,34.29 r180 top
C40S "10nF" CC1608-0603#1 76.75,49.6 r90 top
C41 "2.2uF/50V/Bip" "CAP D5mm/P2mm" 40.767,20.32 r180 top
C41S "10nF" CC1608-0603#2 86.55,38 r270 bottom
C42S "10nF" CC1608-0603#1 86.55,32 r90 bottom
C43S "10nF" CC1608-0603#1 84.55,30 r90 bottom
C44S "220nF" CC1608-0603#1 84.55,40 r270 bottom
C45S "10nF" CC1608-0603#1 76.55,40 r90 bottom
C46S "10nF" CC1608-0603#1 86.55,28 r270 bottom
C47S "10nF" CC1608-0603#1 80.55,30 r90 bottom
C48S "220nF" CC1608-0603#1 88.55,30 r270 bottom
C49S "10nF" CC1608-0603#1 78.55,38 r270 bottom
C50S "10nF" CC1608-0603#1 78.55,28 r270 bottom
C51S "470uF 16V" RB8/3.5 89.15,14.3 r0 top
C52S "470uF 16V" RB8/3.5 75.95,14.3 r0 top
C53S "470uF 16V" RB8/3.5 120.75,35.8 r180 top
C54S "10uF" MCCT-B#1 63.15,48.2 r90 top
C55S "10uF" MCCT-B#1 48.45,39.9 r90 top
C56S "10uF" MCCT-B#1 113.95,15.3 r0 top
C57S "10uF" MCCT-B#1 82.55,14.2 r270 top
C58S "10uF" MCCT-B#1 67.15,48.2 r90 top
C59S "10uF" MCCT-B#1 100.75,49 r90 top
C60S "10uF" MCCT-B#2 97.15,29.4 r270 top
C61S "47pF" CC2012-0805 154.55,79.2 r270 top
C62S "47pF" CC2012-0805 160.95,99 r90 top
C63S "47pF" CC2012-0805 159.75,79.2 r270 top
C64S "47pF" CC2012-0805 157.15,79.2 r270 top
C65S "47pF" CC2012-0805 134.95,99 r270 top
C66S "47pF" CC2012-0805 151.95,79.2 r270 top
C67S "47pF" CC2012-0805 149.35,79.2 r270 top
C68S "100nF" CC2012-0805 158,74.6 r180 top
C69S "470uF 16V" RB8/3.5 88.55,104.2 r90 top
C70S "470uF 16V" RB8/3.5 114.3,104.14 r90 top
C71S "470uF 16V" RB8/3.5 159.95,47.8 r0 top
C72S "470uF 16V" RB8/3.5 160,27.2 r0 top
C73S "10uF" MCCT-B#1 18.95,63.6 r270 top
C74S "10uF" MCCT-B#1 13.95,62.6 r0 top
C75S "10uF" MCCT-B#1 153.67,53.975 r90 top
C76S "10uF" MCCT-B#1 153.67,48.26 r270 top
C77S "10uF" MCCT-B#1 153.67,33.655 r90 top
C78S "10uF" MCCT-B#1 153.67,27.305 r270 top
C79S "10uF" MCCT-B#1 159.55,19.4 r270 top
C80S "220nF" CC1608-0603#1 82.55,28 r270 bottom
CR1 "50MHz QC49/SMD" QC49/SMD 123.19,26.035 r0 top
D1S "SMBJ5341B" DO214 112.15,111.8 r180 top
D2S "BAS40-04" SO-G3 161.925,11.43 r180 top
DS1 "HDSP-513A" SA/SC56 45.72,75.565 r0 top locked
DS2 "HDSP-513A" SA/SC56 58.42,75.565 r0 top locked
DS3 "HDSP-513A" SA/SC56 71.12,75.565 r0 top locked
DS4 "HDSP-513A" SA/SC56 83.82,75.565 r0 top locked
DS5 "HDSP-513A" SA/SC56 96.52,75.565 r0 top locked
DS6 "HDSP-513A" SA/SC56 109.22,75.565 r0 top locked
FPGA1S "XC3S400-5FG456C" FG456 82.55,34.9 r0 top
GJ1S "Header 2" HDR1X2 32.75,14.86 r90 top
GJ2S "Header 2" HDR1X2 159.385,40.005 r270 top
GJ3S "Header 2" HDR1X2 49.05,111.2 r270 top
GJ4S "Header 2" HDR1X2 108.69,21.6 r180 top
HDR1 "Header 10X2" HDR2X10 81.915,3.81 r0 top locked
HDR2 "Header 10X2" HDR2X10 117.44,3.81 r0 top locked
J1 "ST-3150-5N" ST-3150-5N 12.05,-0.05 r180 top
J1S "70246-2622" HDR2X13_CEN_LP 156.95,92.6 r180 top
J2 "MDJ-F-06" MDJ-F-06 129.35,114.9 r270 top
J2S "KLD-0202-B" KLD-0202 103.505,114.935 r270 top locked
J3 "MDJ-F-06" MDJ-F-06 146.95,114.9 r270 top
J4 "DB9 Female" DSUB1.385-2H9 27.305,114.935 r0 top locked
J5 "Dsub-15-Female-HD" DB15-VGA-Female 62.484,100.965 r0 top locked
J6 "ST-3150-5N" ST-3150-5N 23.55,-0.05 r180 top
JP1 "Header 2X2" HDR2X2_B 74.295,3.81 r0 top locked
JP2 "Header 2X2" HDR2X2_B 109.855,3.81 r0 top locked
L1 "470nH" CR2012-0805#1 115.55,18.4 r180 top
LD0 "HSMH-C170" "SMD _LED" 49.53,19.685 r90 top
LD1 "HSMH-C170" "SMD _LED" 52.07,19.685 r90 top
LD2 "HSMH-C170" "SMD _LED" 54.61,19.685 r90 top
LD3 "HSMH-C170" "SMD _LED" 57.15,19.685 r90 top
LD4 "HSMH-C170" "SMD _LED" 59.69,19.685 r90 top
LD5 "HSMH-C170" "SMD _LED" 62.23,19.685 r90 top
LD6 "HSMH-C170" "SMD _LED" 64.77,19.685 r90 top
LD7 "HSMH-C170" "SMD _LED" 67.31,19.685 r90 top
LED1 "HSMH-C170" "SMD _LED" 95.25,102.87 r270 top
LED2 "HSMG-C170" "SMD _LED" 148.95,14 r0 top
LED4 "HSMH-C170" "SMD _LED" 40.95,98.4 r90 top
LED5 "HSMH-C170" "SMD _LED" 31.15,98.4 r90 top
LED6 "HSMH-C170" "SMD _LED" 37.55,98.4 r90 top
LED7 "HSMH-C170" "SMD _LED" 27.75,98.4 r90 top
Logo1 "Altium" Altium 26.054,88.411 r0 top
Logo2 "Live Design Evaluation Board" "Live Design Evaluation Board" 25.546,42.564 r0 top
Logo3 "Serial Number Area" "Serial Number" 85.998,93.11 r0 top
LS1 "Speaker" PIN2 133.35,58.42 r0 top
LS2 "Speaker" PIN2 29.21,58.42 r0 top
P1 "R09A12V01-A502-15E (2x5k log)" R09A12V01-E 40.55,10.16 r0 top
R1 "10R" CR2012-0805#1 6.75,10.8 r0 top
R1S "4k7" CR2012-0805#1 93.75,20.8 r90 top
R2 "68R" CR2012-0805#1 6.75,13.4 r0 top
R2S "4k7" CR2012-0805#1 72.05,49.6 r0 top
R3 "68R" CR2012-0805#1 23.15,19.8 r180 top
R3S "4k7" CR2012-0805#1 70.55,20.6 r90 top
R4 "100k" CR2012-0805#1 2.55,10.8 r180 top
R4S "4k7" CR2012-0805#1 73.15,20.6 r90 top
R5 "100k" CR2012-0805#1 23.35,23 r90 top
R5S "4k7" CR2012-0805#1 148.75,71.8 r180 top
R6 "10R" CR2012-0805#1 4.35,40.4 r90 top
R6S "4k7" CR2012-0805#1 159.55,60.6 r0 top
R7 "6K8" CR2012-0805#1 5.75,24 r270 top
R7S "4k7" CR2012-0805#1 148.75,60.8 r180 top
R8 "6K8" CR2012-0805#1 2.75,24 r90 top
R8S "4k7" CR2012-0805#1 148.75,63.4 r0 top
R9 "4k7" CR2012-0805#1 45.95,60.8 r90 top
R9S "100R" CR2012-0805#1 148.75,69.2 r180 top
R10 "4k7" CR2012-0805#1 58.55,61 r90 top
R10S "100R" CR2012-0805#1 159.55,58 r0 top
R11 "4k7" CR2012-0805#1 46.55,3.4 r90 bottom
R11S "100R" CR2012-0805#1 148.75,66.6 r180 top
R12 "4k7" CR2012-0805#1 48.26,8.255 r90 bottom
R12S "100R" CR2012-0805#1 152.55,63.4 r180 top
R13 "4k7" CR2012-0805#1 52.07,7.62 r90 bottom
R13S "4k7" CR2012-0805#1 151.95,83.8 r90 top
R14 "4k7" CR2012-0805#1 55.88,8.255 r90 bottom
R14S "4k7" CR2012-0805#1 150.55,99 r270 top
R15 "4k7" CR2012-0805#1 59.69,7.62 r90 bottom
R15S "4k7" CR2012-0805#1 145.35,99 r270 top
R16 "4k7" CR2012-0805#1 63.5,8.255 r90 bottom
R16S "4k7" CR2012-0805#1 142.75,99 r270 top
R17 "4k7" CR2012-0805#1 67.31,7.62 r90 bottom
R17S "4k7" CR2012-0805#1 140.15,99 r270 top
R18 "4k7" CR2012-0805#1 73.75,9.8 r90 bottom
R18S "4k7" CR2012-0805#1 132.35,99 r270 top
R19 "4k7" CR2012-0805#1 71.15,61 r90 top
R19S "4k7" CR2012-0805#1 129.75,99 r270 top
R20 "4k7" CR2012-0805#1 83.95,61 r90 top
R20S "4k7" CR2012-0805#1 147.95,99 r270 top
R21 "4k7" CR2012-0805#1 157.75,13.2 r270 top
R21S "100R" CR2012-0805#1 124.55,99 r270 top
R22 "4k7" CR2012-0805#1 96.52,60.96 r90 top
R22S "100R" CR2012-0805#1 159.55,63.2 r180 top
R23 "4k7" CR2012-0805#1 109.22,60.96 r90 top
R23S "100R" CR2012-0805#1 146.75,83.8 r90 top
R24 "100R" CR2012-0805#1 133.55,13.4 r90 top
R24S "100R" CR2012-0805#1 149.35,83.8 r90 top
R25 "270R" CR2012-0805#1 52.705,86.995 r270 bottom
R25S "100R" CR2012-0805#1 137.55,99 r90 top
R26 "270R" CR2012-0805#1 65.405,86.995 r270 bottom
R26S "100R" CR2012-0805#1 157.15,83.8 r90 top
R27 "270R" CR2012-0805#1 78.105,86.995 r270 bottom
R27S "100R" CR2012-0805#1 159.75,83.8 r90 top
R28 "270R" CR2012-0805#1 90.805,86.995 r270 bottom
R28S "100R" CR2012-0805#1 153.15,99 r90 top
R29 "270R" CR2012-0805#1 55.88,85.725 r270 bottom
R29S "100R" CR2012-0805#1 154.55,83.8 r90 top
R30 "270R" CR2012-0805#1 68.58,85.725 r270 bottom
R30S "4k7" CR2012-0805#1 163.35,20.2 r90 top
R31 "270R" CR2012-0805#1 81.28,85.725 r270 bottom
R31S "10R" CR2012-0805#1 154.94,20.32 r180 top
R32 "270R" CR2012-0805#1 93.98,85.725 r270 bottom
R32S "120R 1%" CR2012-0805#1 9.75,61.6 r270 top
R33 "270R" CR2012-0805#1 52.705,80.645 r90 bottom
R33S "120R 1%" CR2012-0805#1 154.94,43.815 r0 top
R34 "270R" CR2012-0805#1 65.405,80.645 r90 bottom
R34S "120R 1%" CR2012-0805#1 154.94,41.275 r180 top
R35 "270R" CR2012-0805#1 78.105,80.645 r90 bottom
R35S "220R 1%" CR2012-0805#1 4.55,61.6 r270 top
R36 "270R" CR2012-0805#1 90.805,80.645 r90 bottom
R36S "1K8 1%" CR2012-0805#1 7.15,61.6 r270 top
R37 "270R" CR2012-0805#1 49.53,79.375 r90 bottom
R37S "Do Not Mount" CR2012-0805#1 154.94,22.86 r0 top
R38 "270R" CR2012-0805#1 62.23,79.375 r90 bottom
R38S "470R" CR2012-0805#1 161.75,15 r0 top
R39 "270R" CR2012-0805#1 74.93,79.375 r90 bottom
R40 "270R" CR2012-0805#1 87.63,79.375 r90 bottom
R41 "270R" CR2012-0805#1 46.35,80.62 r90 bottom
R42 "270R" CR2012-0805#1 59.055,80.645 r90 bottom
R43 "270R" CR2012-0805#1 71.755,80.645 r90 bottom
R44 "270R" CR2012-0805#1 84.455,80.645 r90 bottom
R45 "270R" CR2012-0805#1 49.53,85.725 r270 bottom
R46 "270R" CR2012-0805#1 62.23,85.725 r270 bottom
R47 "270R" CR2012-0805#1 74.93,85.725 r270 bottom
R48 "270R" CR2012-0805#1 87.63,85.725 r270 bottom
R49 "270R" CR2012-0805#1 46.355,86.995 r270 bottom
R50 "270R" CR2012-0805#1 59.055,86.995 r270 bottom
R51 "270R" CR2012-0805#1 71.755,86.995 r270 bottom
R52 "270R" CR2012-0805#1 84.455,86.995 r270 bottom
R53 "270R" CR2012-0805#1 55.88,79.375 r90 bottom
R54 "270R" CR2012-0805#2 68.58,79.375 r90 bottom
R55 "270R" CR2012-0805#1 81.35,79.42 r90 bottom
R56 "270R" CR2012-0805#1 93.98,79.375 r90 bottom
R57 "270R" CR2012-0805#1 103.505,86.995 r270 bottom
R58 "270R" CR2012-0805#1 116.205,86.995 r270 bottom
R59 "270R" CR2012-0805#1 106.68,85.725 r270 bottom
R60 "270R" CR2012-0805#1 119.38,85.725 r270 bottom
R61 "270R" CR2012-0805#3 103.55,80.62 r90 bottom
R62 "270R" CR2012-0805#1 116.205,80.645 r90 bottom
R63 "270R" CR2012-0805#1 100.35,79.42 r90 bottom
R64 "270R" CR2012-0805#1 113.03,79.375 r90 bottom
R65 "270R" CR2012-0805#1 97.15,80.62 r90 bottom
R66 "270R" CR2012-0805#1 109.855,80.645 r90 bottom
R67 "270R" CR2012-0805#1 100.33,85.725 r270 bottom
R68 "270R" CR2012-0805#1 113.03,85.725 r270 bottom
R69 "270R" CR2012-0805#1 97.155,86.995 r270 bottom
R70 "270R" CR2012-0805#1 109.855,86.995 r270 bottom
R71 "270R" CR2012-0805#1 106.68,79.375 r90 bottom
R72 "270R" CR2012-0805#1 119.38,79.375 r90 bottom
R73 "270R" CR2012-0805#1 155.15,13.2 r90 top
R74 "270R" CR2012-0805#1 49.53,15.24 r90 top
R75 "270R" CR2012-0805#1 52.07,15.24 r90 top
R76 "270R" CR2012-0805#1 54.61,15.24 r90 top
R77 "270R" CR2012-0805#1 57.15,15.24 r90 top
R78 "270R" CR2012-0805#1 59.69,15.24 r90 top
R79 "270R" CR2012-0805#1 62.23,15.24 r90 top
R80 "270R" CR2012-0805#1 64.77,15.24 r90 top
R81 "270R" CR2012-0805#1 67.31,15.24 r90 top
R82 "2k2" CR2012-0805#1 130.95,13.4 r90 top
R83 "390R" CR2012-0805#1 95.25,107.315 r270 top
R84 "4k7" CR2012-0805#1 155.75,99 r270 top
R85 "4k7" CR2012-0805#1 156.15,103.4 r270 top
R86 "4k7" CR2012-0805#1 120.35,103.6 r270 top
R87 "4k7" CR2012-0805#1 127.15,99 r90 top
R88 "100R" CR2012-0805#1 121.95,99 r90 top
R89 "100R" CR2012-0805#1 119.35,99 r90 top
R90 "100R" CR2012-0805#1 34.35,98.4 r270 top
R91 "100R" CR2012-0805#1 24.325,99.375 r180 top
R92 "100R" CR2012-0805#1 123.825,83.82 r90 top
R93 "100R" CR2012-0805#1 158.35,99 r270 top
R94 "100R" CR2012-0805#1 48.35,100 r90 top
R95 "100R" CR2012-0805#1 79.55,95 r90 top
R96 "270R" CR2012-0805#1 45.75,100 r270 top
R97 "270R" CR2012-0805#1 45.75,104.4 r90 top
R98 "270R" CR2012-0805#1 48.35,104.4 r90 top
R99 "270R" CR2012-0805#1 45.75,108.6 r270 top
R100 "680R" CR2012-0805#1 56.15,95 r90 top
R101 "680R" CR2012-0805#1 53.55,95 r90 top
R102 "680R" CR2012-0805#1 50.95,95 r90 top
R103 "680R" CR2012-0805#1 61.35,95 r90 top
R104 "680R" CR2012-0805#1 58.75,95 r90 top
R105 "680R" CR2012-0805#1 63.95,95 r90 top
R106 "680R" CR2012-0805#1 71.75,95 r90 top
R107 "680R" CR2012-0805#1 69.15,95 r90 top
R108 "680R" CR2012-0805#1 74.35,95 r90 top
R109 "330R" CR2012-0805#1 48.35,95 r90 top
R110 "330R" CR2012-0805#1 66.55,95 r90 top
R111 "330R" CR2012-0805#1 76.95,95 r90 top
R112 "470K" CR2012-0805#1 124.46,20.955 r0 top
R113 "10R" CR2012-0805#1 19.35,19.8 r180 top
R114 "do not mount" CR2012-0805#1 40.35,12.8 r0 top
R115 "do not mount" CR2012-0805#1 32.75,7.4 r90 top
R116 "22k" CR2012-0805#1 18.15,45.8 r0 top
R117 "22k" CR2012-0805#1 5.15,48.4 r0 top
R118 "33k" CR2012-0805#1 18.15,48.4 r180 top
R119 "33k" CR2012-0805#1 5.15,51 r0 top
R120 "10k" CR2012-0805#1 15.4,58.6 r0 top
R121 "10k" CR2012-0805#1 11.35,58.6 r180 top
R122 "47R" CR2012-0805#1 115.35,12.2 r0 top
RN1 "10X-102-4k7" SIL-10/X1.2 14.605,36.195 r180 top
RN2 "10X-102-4k7" SIL-10/X1.2 14.605,28.575 r180 top
S1 "A6ER-8104" DIP-16-KEY 49.53,4 r0 top locked
SW1 "DTSM-61-NR" B3FS_SWITCH 50.8,57.785 r270 top locked
SW2 "DTSM-61-NR" B3FS_SWITCH 63.5,57.785 r270 top locked
SW3 "DTSM-61-NR" B3FS_SWITCH 76.2,57.785 r270 top locked
SW4 "DTSM-61-NR" B3FS_SWITCH 88.9,57.785 r270 top locked
SW5 "DTSM-61-NR" B3FS_SWITCH 101.6,57.785 r270 top locked
SW6 "DTSM-61-NR" B3FS_SWITCH 114.3,57.785 r270 top locked
SW7 "DTSM-61-NR" B3FS_SWITCH 148.95,8.2 r180 top
TP1S "(TDI)" TestPin 148.55,74.8 r270 top
TP2S "(TDO)" TestPin 154.95,60.2 r0 top
TP3S "(TCK)" TestPin 147.35,57.6 r0 top
TP4S "(TMS)" TestPin 151.75,60.2 r0 top
TP5S "(2V50)" TestPin 160.655,54.61 r90 top
TP6S "(5V)" TestPin 118.95,111.8 r90 top
TP7S "(3V3)" TestPin 45.95,57.2 r90 top
TP8S "(1V20)" TestPin 160.655,34.29 r90 top
U1 "LM4880M" M08A 11.75,50.6 r90 top
U1S "SN74LV244W" SSO-G20/P.65 156.15,69.2 r270 top
U2 "LMV358M" M08A 14.55,22.6 r0 top
U2S "LM1084IS-ADJ" TO-263 7.61,66.95 r0 top
U3 "SN74LV04D" D014 121.92,15.24 r180 top
U3S "LM1084IS-ADJ" TO-263 148.55,46 r90 top
U4 "MAX3232CSE" TSSO5x6-G16 19.55,96.6 r0 top
U4S "LM1084IS-ADJ" TO-263 148.55,23.495 r90 top
U5 "SRAM 256Kx16 TSOP44" SO-G44/P.8 57.785,34.29 r270 top
U6 "SRAM 256Kx16 TSOP44" SO-G44/P.8 107.15,34.2 r270 top

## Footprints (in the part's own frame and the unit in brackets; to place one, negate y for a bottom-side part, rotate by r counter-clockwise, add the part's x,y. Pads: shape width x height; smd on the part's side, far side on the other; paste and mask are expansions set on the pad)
Altium [mm] "Altium Logo"
  silkscreen extent 0,-0.08 17.6,3.84
B3FS_SWITCH [mm]
  rect 1.6x1.4 smd: 1(4.01,-2.25) 2(-4,-2.25) 3(4.01,2.24) 4(-4,2.24)
  silkscreen extent -3.16,-3.16 3.15,3.15
"CAP D5MM/P2MM" [mil]
  rect 60x60 hole 28: 1(0,0)
  round 60 hole 28: 2(78.74,0)
  silkscreen extent -59,-98 138,98
"CAP D5mm/P2mm" [mil]
  rect 60x60 hole 28: 1(0,0)
  round 60 hole 28: 2(78.74,0)
  silkscreen extent -59,-98 138,98
CC1608-0603#1 [mm]
  rect 1.1x1 smd: 1(-0.85,0) 2(0.85,0)
  silkscreen extent -0.85,-0.75 0.85,0.75
CC1608-0603#2 [mm]
  rect 1.1x1 smd: 1(-0.85,0) 2(0.9,0)
  silkscreen extent -0.85,-0.75 0.85,0.75
CC2012-0805 [mm]
  rect 1.3x1.5 smd: 1(-0.95,0) 2(0.95,0)
  silkscreen extent -1.1,-1 1.1,1
CC3216-1206 [mm]
  rect 1.6x1.8 smd: 1(-1.4,0) 2(1.4,0)
  silkscreen extent -1.7,-1.15 1.7,1.15
CR2012-0805#1 [mm]
  rect 1.3x1.5 smd: 1(-0.95,0) 2(0.95,0)
  silkscreen extent -1.1,-1 1.1,1
CR2012-0805#2 [mm]
  rect 1.3x1.5 smd: 1(-0.95,0) 2(0.972,0.043)
  silkscreen extent -1.1,-1 1.1,1
CR2012-0805#3 [mm]
  rect 1.3x1.5 smd: 1(-0.945,-0.01) 2(0.95,0)
  silkscreen extent -1.1,-1 1.1,1
D014 [mm] "Small Outline; 14 Leads; Body Width 3.9 mm; Pitch 1.27 mm"
  rect 0.6x2.05 smd: 1(-3.81,-2.675) 2(-2.54,-2.675) 3(-1.27,-2.675) 4(0,-2.675) 5(1.27,-2.675) 6(2.54,-2.675) 7(3.81,-2.675) 8(3.81,2.675) 9(2.54,2.675) 10(1.27,2.675) 11(0,2.675) 12(-1.27,2.675) 13(-2.54,2.675) 14(-3.81,2.675)
  silkscreen extent -4.78,-2.8 4.38,1.25
DB15-VGA-Female [mm]
  rect 1.6x1.6 hole 1.1: 1(0,0)
  round 1.6 hole 1.1: 2(2.29,0) 3(4.58,0) 4(6.87,0) 5(9.16,0) 6(-1.4,2.54) 7(0.89,2.54) 8(3.18,2.54) 9(5.47,2.54) 10(7.76,2.54) 11(0,5.08) 12(2.29,5.08) 13(4.58,5.08) 14(6.87,5.08) 15(9.16,5.08)
  round 5 hole 3.3: 16(-7.915,2.54) 17(17.075,2.54)
  silkscreen extent -10.83,-2.65 20.01,19.61
DIP-16-KEY [mm]
  rect 1.5x1.5 hole 0.9: 1(0,0)
  round 1.5 hole 0.9: 2(2.54,0) 3(5.08,0) 4(7.62,0) 5(10.16,0) 6(12.7,0) 7(15.24,0) 8(17.78,0) 9(17.78,7.62) 10(15.24,7.62) 11(12.7,7.62) 12(10.16,7.62) 13(7.62,7.62) 14(5.08,7.62) 15(2.54,7.62) 16(0,7.62)
  silkscreen extent -2.05,-1.59 19.83,9.2
DO214 [mil]
  rect 85x110 smd: 1(-87.5,0) 2(87.5,0)
  silkscreen extent -90,-78 90,78
DSUB1.385-2H9 [mm]
  rect 1.69x1.69 hole 1.1: 1(-5.54,-10.92)
  round 1.69 hole 1.1: 2(-2.77,-10.92) 3(0,-10.92) 4(2.77,-10.92) 5(5.54,-10.92) 6(-4.155,-8.08) 7(-1.385,-8.08) 8(1.385,-8.08) 9(4.155,-8.08)
  round 4.76 hole 3.3: 10(-12.495,-9.5) 11(12.495,-9.5)
  silkscreen extent -15.4,-12.4 15.4,6
FG456 [mm] "456-Ball Fine Pitch Ball Grid Array (FG456)"
  round 0.4 smd mask+0.1: A1(-10.5,10.5) A2(-9.5,10.5) A3(-8.5,10.5) A4(-7.5,10.5) A5(-6.5,10.5) A6(-5.5,10.5) A7(-4.5,10.5) A8(-3.5,10.5) A9(-2.5,10.5) A10(-1.5,10.5) A11(-0.5,10.5) A12(0.5,10.5) A13(1.5,10.5) A14(2.5,10.5) A15(3.5,10.5) A16(4.5,10.5) A17(5.5,10.5) A18(6.5,10.5) A19(7.5,10.5) A20(8.5,10.5) A21(9.5,10.5) A22(10.5,10.5) AA1(-10.5,-9.5) AA2(-9.5,-9.5) AA3(-8.5,-9.5) AA4(-7.5,-9.5) AA5(-6.5,-9.5) AA6(-5.5,-9.5) AA7(-4.5,-9.5) AA8(-3.5,-9.5) AA9(-2.5,-9.5) AA10(-1.5,-9.5) AA11(-0.5,-9.5) AA12(0.5,-9.5) AA13(1.5,-9.5) AA14(2.5,-9.5) AA15(3.5,-9.5) AA16(4.5,-9.5) AA17(5.5,-9.5) AA18(6.5,-9.5) AA19(7.5,-9.5) AA20(8.5,-9.5) AA21(9.5,-9.5) AA22(10.5,-9.5) AB1(-10.5,-10.5) AB2(-9.5,-10.5) AB3(-8.5,-10.5) AB4(-7.5,-10.5) AB5(-6.5,-10.5) AB6(-5.5,-10.5) AB7(-4.5,-10.5) AB8(-3.5,-10.5) AB9(-2.5,-10.5) AB10(-1.5,-10.5) AB11(-0.5,-10.5) AB12(0.5,-10.5) AB13(1.5,-10.5) AB14(2.5,-10.5) AB15(3.5,-10.5) AB16(4.5,-10.5) AB17(5.5,-10.5) AB18(6.5,-10.5) AB19(7.5,-10.5) AB20(8.5,-10.5) AB21(9.5,-10.5) AB22(10.5,-10.5) B1(-10.5,9.5) B2(-9.5,9.5) B3(-8.5,9.5) B4(-7.5,9.5) B5(-6.5,9.5) B6(-5.5,9.5) B7(-4.5,9.5) B8(-3.5,9.5) B9(-2.5,9.5) B10(-1.5,9.5) B11(-0.5,9.5) B12(0.5,9.5) B13(1.5,9.5) B14(2.5,9.5) B15(3.5,9.5) B16(4.5,9.5) B17(5.5,9.5) B18(6.5,9.5) B19(7.5,9.5) B20(8.5,9.5) B21(9.5,9.5) B22(10.5,9.5) C1(-10.5,8.5) C2(-9.5,8.5) C3(-8.5,8.5) C4(-7.5,8.5) C5(-6.5,8.5) C6(-5.5,8.5) C7(-4.5,8.5) C8(-3.5,8.5) C9(-2.5,8.5) C10(-1.5,8.5) C11(-0.5,8.5) C12(0.5,8.5) C13(1.5,8.5) C14(2.5,8.5) C15(3.5,8.5) C16(4.5,8.5) C17(5.5,8.5) C18(6.5,8.5) C19(7.5,8.5) C20(8.5,8.5) C21(9.5,8.5) C22(10.5,8.5) D1(-10.5,7.5) D2(-9.5,7.5) D3(-8.5,7.5) D4(-7.5,7.5) D5(-6.5,7.5) D6(-5.5,7.5) D7(-4.5,7.5) D8(-3.5,7.5) D9(-2.5,7.5) D10(-1.5,7.5) D11(-0.5,7.5) D12(0.5,7.5) D13(1.5,7.5) D14(2.5,7.5) D15(3.5,7.5) D16(4.5,7.5) D17(5.5,7.5) D18(6.5,7.5) D19(7.5,7.5) D20(8.5,7.5) D21(9.5,7.5) D22(10.5,7.5) E1(-10.5,6.5) E2(-9.5,6.5) E3(-8.5,6.5) E4(-7.5,6.5) E5(-6.5,6.5) E6(-5.5,6.5) E7(-4.5,6.5) E8(-3.5,6.5) E9(-2.5,6.5) E10(-1.5,6.5) E11(-0.5,6.5) E12(0.5,6.5) E13(1.5,6.5) E14(2.5,6.5) E15(3.5,6.5) E16(4.5,6.5) E17(5.5,6.5) E18(6.5,6.5) E19(7.5,6.5) E20(8.5,6.5) E21(9.5,6.5) E22(10.5,6.5) F1(-10.5,5.5) F2(-9.5,5.5) F3(-8.5,5.5) F4(-7.5,5.5) F5(-6.5,5.5) F6(-5.5,5.5) F7(-4.5,5.5) F8(-3.5,5.5) F9(-2.5,5.5) F10(-1.5,5.5) F11(-0.5,5.5) F12(0.5,5.5) F13(1.5,5.5) F14(2.5,5.5) F15(3.5,5.5) F16(4.5,5.5) F17(5.5,5.5) F18(6.5,5.5) F19(7.5,5.5) F20(8.5,5.5) F21(9.5,5.5) F22(10.5,5.5) G1(-10.5,4.5) G2(-9.5,4.5) G3(-8.5,4.5) G4(-7.5,4.5) G5(-6.5,4.5) G6(-5.5,4.5) G7(-4.5,4.5) G8(-3.5,4.5) G9(-2.5,4.5) G10(-1.5,4.5) G11(-0.5,4.5) G12(0.5,4.5) G13(1.5,4.5) G14(2.5,4.5) G15(3.5,4.5) G16(4.5,4.5) G17(5.5,4.5) G18(6.5,4.5) G19(7.5,4.5) G20(8.5,4.5) G21(9.5,4.5) G22(10.5,4.5) H1(-10.5,3.5) H2(-9.5,3.5) H3(-8.5,3.5) H4(-7.5,3.5) H5(-6.5,3.5) H6(-5.5,3.5) H7(-4.5,3.5) H16(4.5,3.5) H17(5.5,3.5) H18(6.5,3.5) H19(7.5,3.5) H20(8.5,3.5) H21(9.5,3.5) H22(10.5,3.5) J1(-10.5,2.5) J2(-9.5,2.5) J3(-8.5,2.5) J4(-7.5,2.5) J5(-6.5,2.5) J6(-5.5,2.5) J7(-4.5,2.5) J9(-2.5,2.5) J10(-1.5,2.5) J11(-0.5,2.5) J12(0.5,2.5) J13(1.5,2.5) J14(2.5,2.5) J16(4.5,2.5) J17(5.5,2.5) J18(6.5,2.5) J19(7.5,2.5) J20(8.5,2.5) J21(9.5,2.5) J22(10.5,2.5) K1(-10.5,1.5) K2(-9.5,1.5) K3(-8.5,1.5) K4(-7.5,1.5) K5(-6.5,1.5) K6(-5.5,1.5) K7(-4.5,1.5) K9(-2.5,1.5) K10(-1.5,1.5) K11(-0.5,1.5) K12(0.5,1.5) K13(1.5,1.5) K14(2.5,1.5) K16(4.5,1.5) K17(5.5,1.5) K18(6.5,1.5) K19(7.5,1.5) K20(8.5,1.5) K21(9.5,1.5) K22(10.5,1.5) L1(-10.5,0.5) L2(-9.5,0.5) L3(-8.5,0.5) L4(-7.5,0.5) L5(-6.5,0.5) L6(-5.5,0.5) L7(-4.5,0.5) L9(-2.5,0.5) L10(-1.5,0.5) L11(-0.5,0.5) L12(0.5,0.5) L13(1.5,0.5) L14(2.5,0.5) L16(4.5,0.5) L17(5.5,0.5) L18(6.5,0.5) L19(7.5,0.5) L20(8.5,0.5) L21(9.5,0.5) L22(10.5,0.5) M1(-10.5,-0.5) M2(-9.5,-0.5) M3(-8.5,-0.5) M4(-7.5,-0.5) M5(-6.5,-0.5) M6(-5.5,-0.5) M7(-4.5,-0.5) M9(-2.5,-0.5) M10(-1.5,-0.5) M11(-0.5,-0.5) M12(0.5,-0.5) M13(1.5,-0.5) M14(2.5,-0.5) M16(4.5,-0.5) M17(5.5,-0.5) M18(6.5,-0.5) M19(7.5,-0.5) M20(8.5,-0.5) M21(9.5,-0.5) M22(10.5,-0.5) N1(-10.5,-1.5) N2(-9.5,-1.5) N3(-8.5,-1.5) N4(-7.5,-1.5) N5(-6.5,-1.5) N6(-5.5,-1.5) N7(-4.5,-1.5) N9(-2.5,-1.5) N10(-1.5,-1.5) N11(-0.5,-1.5) N12(0.5,-1.5) N13(1.5,-1.5) N14(2.5,-1.5) N16(4.5,-1.5) N17(5.5,-1.5) N18(6.5,-1.5) N19(7.5,-1.5) N20(8.5,-1.5) N21(9.5,-1.5) N22(10.5,-1.5) P1(-10.5,-2.5) P2(-9.5,-2.5) P3(-8.5,-2.5) P4(-7.5,-2.5) P5(-6.5,-2.5) P6(-5.5,-2.5) P7(-4.5,-2.5) P9(-2.5,-2.5) P10(-1.5,-2.5) P11(-0.5,-2.5) P12(0.5,-2.5) P13(1.5,-2.5) P14(2.5,-2.5) P16(4.5,-2.5) P17(5.5,-2.5) P18(6.5,-2.5) P19(7.5,-2.5) P20(8.5,-2.5) P21(9.5,-2.5) P22(10.5,-2.5) R1(-10.5,-3.5) R2(-9.5,-3.5) R3(-8.5,-3.5) R4(-7.5,-3.5) R5(-6.5,-3.5) R6(-5.5,-3.5) R7(-4.5,-3.5) R16(4.5,-3.5) R17(5.5,-3.5) R18(6.5,-3.5) R19(7.5,-3.5) R20(8.5,-3.5) R21(9.5,-3.5) R22(10.5,-3.5) T1(-10.5,-4.5) T2(-9.5,-4.5) T3(-8.5,-4.5) T4(-7.5,-4.5) T5(-6.5,-4.5) T6(-5.5,-4.5) T7(-4.5,-4.5) T8(-3.5,-4.5) T9(-2.5,-4.5) T10(-1.5,-4.5) T11(-0.5,-4.5) T12(0.5,-4.5) T13(1.5,-4.5) T14(2.5,-4.5) T15(3.5,-4.5) T16(4.5,-4.5) T17(5.5,-4.5) T18(6.5,-4.5) T19(7.5,-4.5) T20(8.5,-4.5) T21(9.5,-4.5) T22(10.5,-4.5) U1(-10.5,-5.5) U2(-9.5,-5.5) U3(-8.5,-5.5) U4(-7.5,-5.5) U5(-6.5,-5.5) U6(-5.5,-5.5) U7(-4.5,-5.5) U8(-3.5,-5.5) U9(-2.5,-5.5) U10(-1.5,-5.5) U11(-0.5,-5.5) U12(0.5,-5.5) U13(1.5,-5.5) U14(2.5,-5.5) U15(3.5,-5.5) U16(4.5,-5.5) U17(5.5,-5.5) U18(6.5,-5.5) U19(7.5,-5.5) U20(8.5,-5.5) U21(9.5,-5.5) U22(10.5,-5.5) V1(-10.5,-6.5) V2(-9.5,-6.5) V3(-8.5,-6.5) V4(-7.5,-6.5) V5(-6.5,-6.5) V6(-5.5,-6.5) V7(-4.5,-6.5) V8(-3.5,-6.5) V9(-2.5,-6.5) V10(-1.5,-6.5) V11(-0.5,-6.5) V12(0.5,-6.5) V13(1.5,-6.5) V14(2.5,-6.5) V15(3.5,-6.5) V16(4.5,-6.5) V17(5.5,-6.5) V18(6.5,-6.5) V19(7.5,-6.5) V20(8.5,-6.5) V21(9.5,-6.5) V22(10.5,-6.5) W1(-10.5,-7.5) W2(-9.5,-7.5) W3(-8.5,-7.5) W4(-7.5,-7.5) W5(-6.5,-7.5) W6(-5.5,-7.5) W7(-4.5,-7.5) W8(-3.5,-7.5) W9(-2.5,-7.5) W10(-1.5,-7.5) W11(-0.5,-7.5) W12(0.5,-7.5) W13(1.5,-7.5) W14(2.5,-7.5) W15(3.5,-7.5) W16(4.5,-7.5) W17(5.5,-7.5) W18(6.5,-7.5) W19(7.5,-7.5) W20(8.5,-7.5) W21(9.5,-7.5) W22(10.5,-7.5) Y1(-10.5,-8.5) Y2(-9.5,-8.5) Y3(-8.5,-8.5) Y4(-7.5,-8.5) Y5(-6.5,-8.5) Y6(-5.5,-8.5) Y7(-4.5,-8.5) Y8(-3.5,-8.5) Y9(-2.5,-8.5) Y10(-1.5,-8.5) Y11(-0.5,-8.5) Y12(0.5,-8.5) Y13(1.5,-8.5) Y14(2.5,-8.5) Y15(3.5,-8.5) Y16(4.5,-8.5) Y17(5.5,-8.5) Y18(6.5,-8.5) Y19(7.5,-8.5) Y20(8.5,-8.5) Y21(9.5,-8.5) Y22(10.5,-8.5)
  silkscreen extent -12.27,-11.5 11.5,11.5
HDR1X2 [mm]
  rect 1.5x1.5 hole 0.9: 1(0,0)
  round 1.5 hole 0.9: 2(2.54,0)
  silkscreen extent -1.27,-1.27 3.81,1.27
HDR2X2_B [mm]
  rect 1.5x1.5 hole 0.9: 1(0,0)
  round 1.5 hole 0.9: 2(0,2.54) 3(2.54,0) 4(2.54,2.54)
  silkscreen extent -1.27,-1.27 3.81,3.81
HDR2X10 [mm]
  rect 1.5x1.5 hole 0.9: 1(0,0)
  round 1.5 hole 0.9: 2(0,2.54) 3(2.54,0) 4(2.54,2.54) 5(5.08,0) 6(5.08,2.54) 7(7.62,0) 8(7.62,2.54) 9(10.16,0) 10(10.16,2.54) 11(12.7,0) 12(12.7,2.54) 13(15.24,0) 14(15.24,2.54) 15(17.78,0) 16(17.78,2.54) 17(20.32,0) 18(20.32,2.54) 19(22.86,0) 20(22.86,2.54)
  silkscreen extent -1.27,-1.27 24.13,3.81
HDR2X13_CEN_LP [mm]
  rect 1.5x1.5 hole 0.9: 1(0,0)
  round 1.5 hole 0.9: 2(2.54,0) 3(5.08,0) 4(7.62,0) 5(10.16,0) 6(12.7,0) 7(15.24,0) 8(17.78,0) 9(20.32,0) 10(22.86,0) 11(25.4,0) 12(27.94,0) 13(30.48,0) 14(0,2.54) 15(2.54,2.54) 16(5.08,2.54) 17(7.62,2.54) 18(10.16,2.54) 19(12.7,2.54) 20(15.24,2.54) 21(17.78,2.54) 22(20.32,2.54) 23(22.86,2.54) 24(25.4,2.54) 25(27.94,2.54) 26(30.48,2.54)
  silkscreen extent -5.08,-3.18 35.56,5.72
KLD-0202 [mm]
  oval 2x4.5 all layers, no hole: 1(13.7,0)
  round 1.5 hole 1: 1A(13.7,-1.25) 1B(13.7,1.25) 2A(7.5,-1) 2B(7.5,1) 3A(9.5,-5) 3B(11.5,-5)
  oval 2x4 all layers, no hole: 2(7.5,0)
  oval 4x2 all layers, no hole: 3(10.5,-5)
  silkscreen extent 0,-4.5 14.6,4.5
"Live Design Evaluation Board" [mm] "Live Design Logo"
  silkscreen extent 0.03,0 33.78,10.44
M08A [mm] "Small Outline; 8 Leads; Body Width 3.9 mm; Pitch 1.27 mm"
  rect 0.6x2.2 smd: 1(-1.905,-2.6) 2(-0.635,-2.6) 3(0.635,-2.6) 4(1.905,-2.6) 5(1.905,2.6) 6(0.635,2.6) 7(-0.635,2.6) 8(-1.905,2.6)
  silkscreen extent -2.88,-2.72 2.5,1.1
MCCT-B#1 [mm]
  rect 2x2.2 smd: 1(-1.5,0) 2(1.5,0)
  silkscreen extent -2.3,-1.6 1.8,1.6
MCCT-B#2 [mm]
  rect 1.9x2.2 smd: 1(-1.5,0) 2(1.5,0)
  silkscreen extent -2.3,-1.6 1.8,1.6
MDJ-F-06 [mm]
  round 1.5 hole 0.9: 1(8.5,-1.3) 2(8.5,1.3) 3(8.5,-3.4) 5(8.5,3.4) 6(11,-3.4) 8(11,3.4)
  round 3.65 hole 2.2: MH1(5.5,-6.75) MH2(4.7,0) MH3(5.5,6.75)
  silkscreen extent 0,-7 12.9,7
PIN2 [mm]
  rect 1.5x1.5 hole 0.9: 1(0,0)
  round 1.5 hole 0.9: 2(2.54,0)
  silkscreen extent -1.4,-1.4 3.94,2.17
QC49/SMD [mm]
  rect 5x2 smd: 1(-4.75,0) 2(4.75,0)
  silkscreen extent -6.75,-2.4 5.7,2.4
R09A12V01-E [mm] "www.sundiode.com/R09A-8.htm"
  round 2 hole 1: 1(0,-3.3) 2(-2.5,-5.8) 3(-2.5,-3.3) 4(2.5,-3.3) 5(2.5,-5.8)
  oval 3x3.5 hole 2.4: 6(5,0) 7(-5,0)
  silkscreen extent -4.9,-15 4.9,2.4
RB8/3.5 [mil]
  rect 70x70 hole 27.56: 1(0,60)
  round 70 hole 27.56: 2(0,-60)
  silkscreen extent -160,-160 160,160
SA/SC56 [mm] "KingBright 14.2mm (0.56\") Single Digit 7 Segment LED Display"
  rect 1.5x1.5 hole 0.7: 1(0,0)
  round 1.5 hole 0.7: 2(2.54,0) 3(5.08,0) 4(7.62,0) 5(10.16,0) 6(10.16,15.24) 7(7.62,15.24) 8(5.08,15.24) 9(2.54,15.24) 10(0,15.24)
  silkscreen extent -1.32,-1.83 11.48,17.07
"Serial Number" [mm] "Serial Number overlay"
  silkscreen extent 0,0 31.89,6.13
SIL-10/X1.2 [mil] "SIP; 10 Leads; Body 5.8 x 25.3 x 2.8 mm (typ); Pitch 2.54 mm"
  rect 60x60 hole 28: 1(-450,0)
  round 60 hole 28: 2(-350,0) 3(-250,0) 4(-150,0) 5(-50,0) 6(50,0) 7(150,0) 8(250,0) 9(350,0) 10(450,0)
  silkscreen extent -516,-59 516,59
"SMD _LED" [mm]
  rect 1.3x1.6 smd: 1(0.95,0) 2(-0.95,0)
  silkscreen extent -2.13,-1.15 2,1.15
SO-G3 [mm]
  rect 0.85x1.3 smd: 1(-0.95,-1.1) 2(0.95,-1.1) 3(0,1.1)
  silkscreen extent -1.95,-1.32 1.95,0.3
SO-G44/P.8 [mm]
  rect 0.45x1.45 smd: 1(-8.4,-5.575) 2(-7.6,-5.575) 3(-6.8,-5.575) 4(-6,-5.575) 5(-5.2,-5.575) 6(-4.4,-5.575) 7(-3.6,-5.575) 8(-2.8,-5.575) 9(-2,-5.575) 10(-1.2,-5.575) 11(-0.4,-5.575) 12(0.4,-5.575) 13(1.2,-5.575) 14(2,-5.575) 15(2.8,-5.575) 16(3.6,-5.575) 17(4.4,-5.575) 18(5.2,-5.575) 19(6,-5.575) 20(6.8,-5.575) 21(7.6,-5.575) 22(8.4,-5.575) 23(8.4,5.575) 24(7.6,5.575) 25(6.8,5.575) 26(6,5.575) 27(5.2,5.575) 28(4.4,5.575) 29(3.6,5.575) 30(2.8,5.575) 31(2,5.575) 32(1.2,5.575) 33(0.4,5.575) 34(-0.4,5.575) 35(-1.2,5.575) 36(-2,5.575) 37(-2.8,5.575) 38(-3.6,5.575) 39(-4.4,5.575) 40(-5.2,5.575) 41(-6,5.575) 42(-6.8,5.575) 43(-7.6,5.575) 44(-8.4,5.575)
  silkscreen extent -9.3,-5.7 9.25,4.45
SSO-G20/P.65 [mm]
  rect 0.4x2.15 smd: 1(-2.925,-3.275) 2(-2.275,-3.275) 3(-1.625,-3.275) 4(-0.975,-3.275) 5(-0.325,-3.275) 6(0.325,-3.275) 7(0.975,-3.275) 8(1.625,-3.275) 9(2.275,-3.275) 10(2.925,-3.275) 11(2.925,3.275) 12(2.275,3.275) 13(1.625,3.275) 14(0.975,3.275) 15(0.325,3.275) 16(-0.325,3.275) 17(-0.975,3.275) 18(-1.625,3.275) 19(-2.275,3.275) 20(-2.925,3.275)
  silkscreen extent -3.8,-3.4 3.75,1.8
ST-3150-5N [mm]
  oval 2.7x1.8 all layers, no hole: 1(-0.85,-5.2) 2(1.15,-7.65) 3(-0.85,-11.35) 4(1.15,-13.25) 5(-0.85,-17)
  round 1.2 hole 1: 1A(-1.3,-5.2) 1B(-0.4,-5.2) 2A(0.7,-7.65) 2B(1.6,-7.65) 3A(-1.3,-11.35) 3B(-0.4,-11.35) 4A(0.7,-13.25) 4B(1.6,-13.25) 5A(-1.3,-17) 5B(-0.4,-17)
  silkscreen extent -4.9,-18 3.2,0
TestPin [mil] "SingleTest Pin"
  round 60 hole 35: 1(0,0)
TO-263 [mm]
  rect 1x3.4 smd: 1(0,0) 2(2.54,0) 3(5.08,0)
  rect 10.25x8.9 smd: 4(2.54,10.45)
  silkscreen extent -3.1,-3.12 8.2,15
TSSO5x6-G16 [mm] "Shrink Small Outline; 16 Leads; Body Width 4.4 mm"
  rect 0.3x1.65 smd: 1(-2.275,-2.775) 2(-1.625,-2.775) 3(-0.975,-2.775) 4(-0.325,-2.775) 5(0.325,-2.775) 6(0.975,-2.775) 7(1.625,-2.775) 8(2.275,-2.775) 9(2.275,2.775) 10(1.625,2.775) 11(0.975,2.775) 12(0.325,2.775) 13(-0.325,2.775) 14(-0.975,2.775) 15(-1.625,2.775) 16(-2.275,2.775)
  silkscreen extent -3.1,-2.9 2.55,1.55

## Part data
C1 C2 C3 C4 C5 C18 C19 C36 C37 C38 C51S C52S C53S C54S C55S C56S C57S C58S C59S C60S C69S C70S C71S C72S C73S C74S C75S C76S C77S C78S C79S: library part CAP_POLAR, "Polar Capacitor"
C1S C2S C3S C4S C5S C6 C6S C7 C7S C8 C8S C9 C9S C10 C10S C11 C11S C12 C12S C13 C13S C14 C14S C15 C15S C16 C16S C17 C17S C18S C19S C20 C20S C21 C21S C22 C22S C23 C23S C24 C24S C25 C25S C26 C26S C27 C27S C28 C28S C29 C29S C30 C30S C31 C31S C32 C32S C33 C33S C34 C34S C35 C35S C36S C37S C38S C39 C39S C40S C41S C42S C43S C44S C45S C46S C47S C48S C49S C50S C61S C62S C63S C64S C65S C66S C67S C68S C80S: library part CAP, "Capacitor"
C40 C41: library part "CAP Electro Bipolar", "Electrolytic Bipolar Capacitor"
CR1: library part QC49/SMD, "SMD Crystal 20MHz HY-Q"
D1S: library part BZG03C13, "Zener Diode, 6.2V, 5W"
D2S: "Shottky Diode Pair"
DS1 DS2 DS3 DS4 DS5 DS6: "14.2 mm General Purpose 7-Segment Display: CC, RH DP"
FPGA1S: "Spartan-3 1.2V FPGA, 264 User I/Os, 456-ball FBGA, High Performance, Commercial Grade"
GJ1S GJ2S GJ3S GJ4S: "Header, 2-Pin"
HDR1 HDR2: "Header, 10-Pin, Dual row"
J1 J6: "3-Conductor Jack with 2 break contacts (normals) and 2 auxiliary make contacts"
J1S: library part "Header 13X2A", "Header, 13-Pin, Dual row"
J2 J3: "Circular DIN, 6 Postion, Jack, Pitch 2.1/2.6 mm"
J2S: "Low Voltage Power Supply Connector"
J4: library part "D Connector 9", "Receptacle Assembly, 9 Position, Right Angle"
J5: "Dsub-15 High density VGA Female connetor"
JP1 JP2: "Header, 2-Pin, Dual row"
L1: library part Inductor, "Inductor"
LD0 LD1 LD2 LD3 LD4 LD5 LD6 LD7 LED1 LED4 LED5 LED6 LED7: library part HSMX-C670, "Typical RED GaAs SMD LED Agilent make"
LED2: library part HSMX-C670, "Typical GREEN GaAs SMD LED Agilent make"
LS1 LS2: "Loudspeaker"
P1: library part "POT Dual Gang Shield", "Alps Stereo Pot"
R1 R1S R2 R2S R3 R3S R4 R4S R5 R5S R6 R6S R7 R7S R8 R8S R9 R9S R10 R10S R11 R11S R12 R12S R13 R13S R14 R14S R15 R15S R16 R16S R17 R17S R18 R18S R19 R19S R20 R20S R21 R21S R22 R22S R23 R23S R24 R24S R25 R25S R26 R26S R27 R27S R28 R28S R29 R29S R30 R30S R31 R31S R32 R32S R33 R33S R34 R34S R35 R35S R36 R36S R37 R37S R38 R38S R39 R40 R41 R42 R43 R44 R45 R46 R47 R48 R49 R50 R51 R52 R53 R54 R55 R56 R57 R58 R59 R60 R61 R62 R63 R64 R65 R66 R67 R68 R69 R70 R71 R72 R73 R74 R75 R76 R77 R78 R79 R80 R81 R82 R83 R84 R85 R86 R87 R88 R89 R90 R91 R92 R93 R94 R95 R96 R97 R98 R99 R100 R101 R102 R103 R104 R105 R106 R107 R108 R109 R110 R111 R112 R113 R114 R115 R116 R117 R118 R119 R120 R121 R122: library part RES, "Resistor"
RN1 RN2: library part 10X-102, "Resistor network SIL 5 individual resistors, 10 pins"
S1: "DIP Switch Side actuator long liver Piano Key"
SW1 SW2 SW3 SW4 SW5 SW6 SW7: library part B3FS, "SPNA SMD Keyboard Switch"
TP1S TP2S TP3S TP4S TP5S TP6S TP7S TP8S: library part TestPin
U1: "Dual 250mW Audio Amplifier with Shutdown Mode"
U1S: library part SN54LV244W, "Octal Buffer/Driver with 3-State Outputs"
U2: "Dual General-Purpose, Low-Voltage Rail-to-Rail Output Operational Amplifier"
U2S U3S U4S: "5A Low Dropout Positive Regulators"
U3: "Hex Inverter"
U4: library part MAX3232EUE, "3.0V TO 5.5V, Low-Power, up to 1Mbps, True RS-232 Transceiver Using Four 0.1µF External Capacitor"
U5 U6: library part "SRAM 512Kx16 TSOP44", "512Kx16Bit SRAM TSOP44"

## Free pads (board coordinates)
  round 8 / inner round 6.35 / far side round 8 hole 3.175: 0(5.08,5.08) 0(5.08,109.931) 0(159.918,5.08) 0(159.969,109.931)
  round 1 smd far side mask+1.8: FID(14.65,111.2) FID(66.55,48.6) FID(96.55,20.4) FID(138.15,104.9) FID(145.15,6.7)
  round 1 smd mask+2: FID(19.55,109.4)
  round 1 smd mask+1.8: FID(69.35,55) FID(97.45,20.1) FID(138.15,105.2)
  round 5 hole 18.5 unplated: H-SPK2(134.62,73.66) H_SPK1(30.48,73.66)
  round 0.3 hole 0.8 unplated: MB(53.1,115.011) MB(53.1,0) MB(54.2,115.011) MB(54.2,0) MB(55.3,115.011) MB(55.3,0) MB(109.8,115.011) MB(109.8,0) MB(110.9,115.011) MB(110.9,0) MB(112,115.011) MB(112,0)
  round 1.6 on Mech2: PSM(1.75,67) PSM(1.75,68.8) PSM(4.25,93.6) PSM(4.3,86.4) PSM(4.3,97.2) PSM(4.35,90) PSM(4.4,70) PSM(5.3,95.4) PSM(5.35,88.2) PSM(5.35,91.8) PSM(5.4,71.8) PSM(5.4,84.6) PSM(6.3,93.6) PSM(6.35,86.4) PSM(6.35,97.2) PSM(6.4,70) PSM(6.4,90) PSM(7.35,71.8) PSM(7.35,91.8) PSM(7.35,95.4) PSM(7.4,84.6) PSM(7.4,88.2) PSM(8.3,93.6) PSM(8.35,86.4) PSM(8.4,70) PSM(8.4,90) PSM(9.35,71.8) PSM(9.35,91.8) PSM(9.4,84.6) PSM(9.4,88.2) PSM(10.3,93.6) PSM(10.35,86.4) PSM(10.35,90) PSM(10.4,70) PSM(11.35,71.8) PSM(11.4,84.6) PSM(11.4,88.2) PSM(12.35,86.4) PSM(12.4,70) PSM(12.4,90) PSM(13.35,71.8) PSM(13.35,84.6) PSM(13.4,88.2) PSM(14.3,86.4) PSM(14.35,67) PSM(14.35,90) PSM(14.4,70) PSM(15.35,71.8) PSM(15.35,84.6) PSM(15.35,88.2) PSM(16.15,67) PSM(16.35,70) PSM(16.35,86.4) PSM(16.4,90) PSM(17.4,77.4) PSM(17.4,81) PSM(17.4,84.6) PSM(17.4,88.2) PSM(18.35,79.2) PSM(18.35,86.4) PSM(18.4,82.8) PSM(18.4,90) PSM(19.4,81) PSM(19.4,84.6) PSM(19.4,88.2) PSM(20.35,82.8) PSM(20.35,86.4) PSM(20.35,90) PSM(21.35,88.2) PSM(21.4,84.6) PSM(22.35,86.4) PSM(22.35,90) PSM(23.35,88.2) PSM(24.35,86.4) PSM(24.35,90) PSM(26.2,87.1) PSM(28.2,87.1) PSM(30.2,87.1) PSM(121.35,52.4) PSM(122.35,47) PSM(122.35,50.6) PSM(122.35,54.2) PSM(123.35,48.8) PSM(123.35,52.4) PSM(124.35,40.3) PSM(124.35,47) PSM(124.35,50.6) PSM(124.35,54.2) PSM(125.35,31.2) PSM(125.35,38.4) PSM(125.35,45.2) PSM(125.35,48.8) PSM(125.35,52.4) PSM(126.35,33) PSM(126.35,36.6) PSM(126.35,40.3) PSM(126.35,43.4) PSM(126.35,47) PSM(126.35,50.6) PSM(126.35,54.2) PSM(127.35,31.2) PSM(127.35,34.8) PSM(127.35,38.4) PSM(127.35,45.2) PSM(127.35,48.8) PSM(127.35,52.4) PSM(128.35,33) PSM(128.35,36.6) PSM(128.35,40.3) PSM(128.35,43.4) PSM(128.35,47) PSM(128.35,50.6) PSM(128.35,54.2) PSM(129.35,31.2) PSM(129.35,34.8) PSM(129.35,38.4) PSM(129.35,45.2) PSM(129.35,48.8) PSM(129.35,52.4) PSM(130.35,29.4) PSM(130.35,33) PSM(130.35,36.6) PSM(130.35,40.3) PSM(130.35,43.4) PSM(130.35,47) PSM(130.35,50.6) PSM(130.35,54.2) PSM(131.35,16.8) PSM(131.35,20.4) PSM(131.35,24) PSM(131.35,27.6) PSM(131.35,31.2) PSM(131.35,34.8) PSM(131.35,38.4) PSM(131.35,45.2) PSM(131.35,48.8) PSM(131.35,52.4) PSM(132.35,18.6) PSM(132.35,22.2) PSM(132.35,25.8) PSM(132.35,29.4) PSM(132.35,33) PSM(132.35,36.6) PSM(132.35,40.3) PSM(133.35,16.8) PSM(133.35,34.8) PSM(133.35,38.4) PSM(134.35,18.6) PSM(134.35,33) PSM(134.35,36.6) PSM(134.35,40.3) PSM(135.35,16.8) PSM(135.35,34.8) PSM(135.35,38.4) PSM(136.35,15) PSM(136.35,18.6) PSM(136.35,33) PSM(136.35,36.6) PSM(136.35,40.3) PSM(137.35,13.2) PSM(137.35,16.8) PSM(137.35,34.8) PSM(137.35,38.4) PSM(138.35,15) PSM(138.35,18.6) PSM(138.35,33) PSM(138.35,36.6) PSM(138.35,40.3) PSM(139.35,16.8) PSM(139.35,13.2) PSM(139.35,34.8) PSM(139.35,38.4) PSM(140.35,18.6) PSM(140.35,15) PSM(140.35,33) PSM(140.35,36.6) PSM(140.35,40.3) PSM(141.35,16.8) PSM(141.35,34.8) PSM(141.35,38.4) PSM(141.35,13.2) PSM(142.35,15) PSM(142.35,18.6) PSM(142.35,33) PSM(142.35,36.6) PSM(142.35,40.3) PSM(143.35,13.2) PSM(143.35,16.8) PSM(143.35,34.8) PSM(143.35,38.4) PSM(144.35,15) PSM(144.35,18.6) PSM(144.35,33) PSM(144.35,36.6) PSM(144.35,40.3) PSM(145.35,13.2) PSM(145.35,20.4) PSM(145.35,31.2) PSM(145.35,16.8) PSM(145.35,34.8) PSM(145.35,38.4) PSM(146.35,33) PSM(146.35,36.6) PSM(146.35,40.3) PSM(146.35,18.6) PSM(147.35,16.8) PSM(147.35,20.4) PSM(147.35,34.8) PSM(147.35,38.4) PSM(148.35,36.6) PSM(148.35,40.3) PSM(148.35,18.6) PSM(149.35,16.8) PSM(149.35,34.8) PSM(149.35,38.4) PSM(149.35,16.8) PSM(149.35,20.4) PSM(150.35,36.6) PSM(150.35,40.3) PSM(150.35,18.6) PSM(151.35,38.4) PSM(151.35,16.8) PSM(152.35,15) PSM(158.75,32)
  rect 1.7x1.7 on Mech2: PSM(29.21,58.42) PSM(133.35,58.42)
  round 20.5 on Mech2: PSM(30.48,73.66) PSM(134.62,73.66)
  round 1.7 on Mech2: PSM(31.75,58.42) PSM(135.89,58.42)

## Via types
v1: diameter 0.6, hole 0.3, Top Layer to Bottom Layer, tented both sides, 427 vias
v2: diameter 1.6, hole 1, Top Layer to Bottom Layer, 224 vias
v3: diameter 0.9, hole 0.5, Top Layer to Bottom Layer, tented both sides, 126 vias
v4: diameter 1.27, hole 0.711, Top Layer to Bottom Layer, tented both sides, 2 vias

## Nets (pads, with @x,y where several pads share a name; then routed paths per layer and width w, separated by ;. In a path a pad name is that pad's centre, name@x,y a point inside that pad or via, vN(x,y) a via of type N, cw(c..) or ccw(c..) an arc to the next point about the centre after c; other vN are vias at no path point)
5VFILT: C3.1 R6.1 R7.1 U2.8 | length 31
  Top Layer w0.6: R6.1@4.35,39.45 4.35,38.2 3.75,37.6 2.15,37.6 1.35,36.8 1.35,27.8 2.35,26.8 9.15,26.8 9.55,26.4 C3.1@9.55,25 ; R7.1@5.75,24.95 9.5,24.95 C3.1@9.55,25 ; C3.1@9.55,24.8 C3.1@9.55,25 ; U2.8@12.55,25 C3.1@9.55,25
